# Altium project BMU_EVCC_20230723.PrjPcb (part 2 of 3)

## Sheet BMU_A2_bq79616.SchDoc
size 558 x 431 mm; SheetNumber: 2; SheetTotal: 9
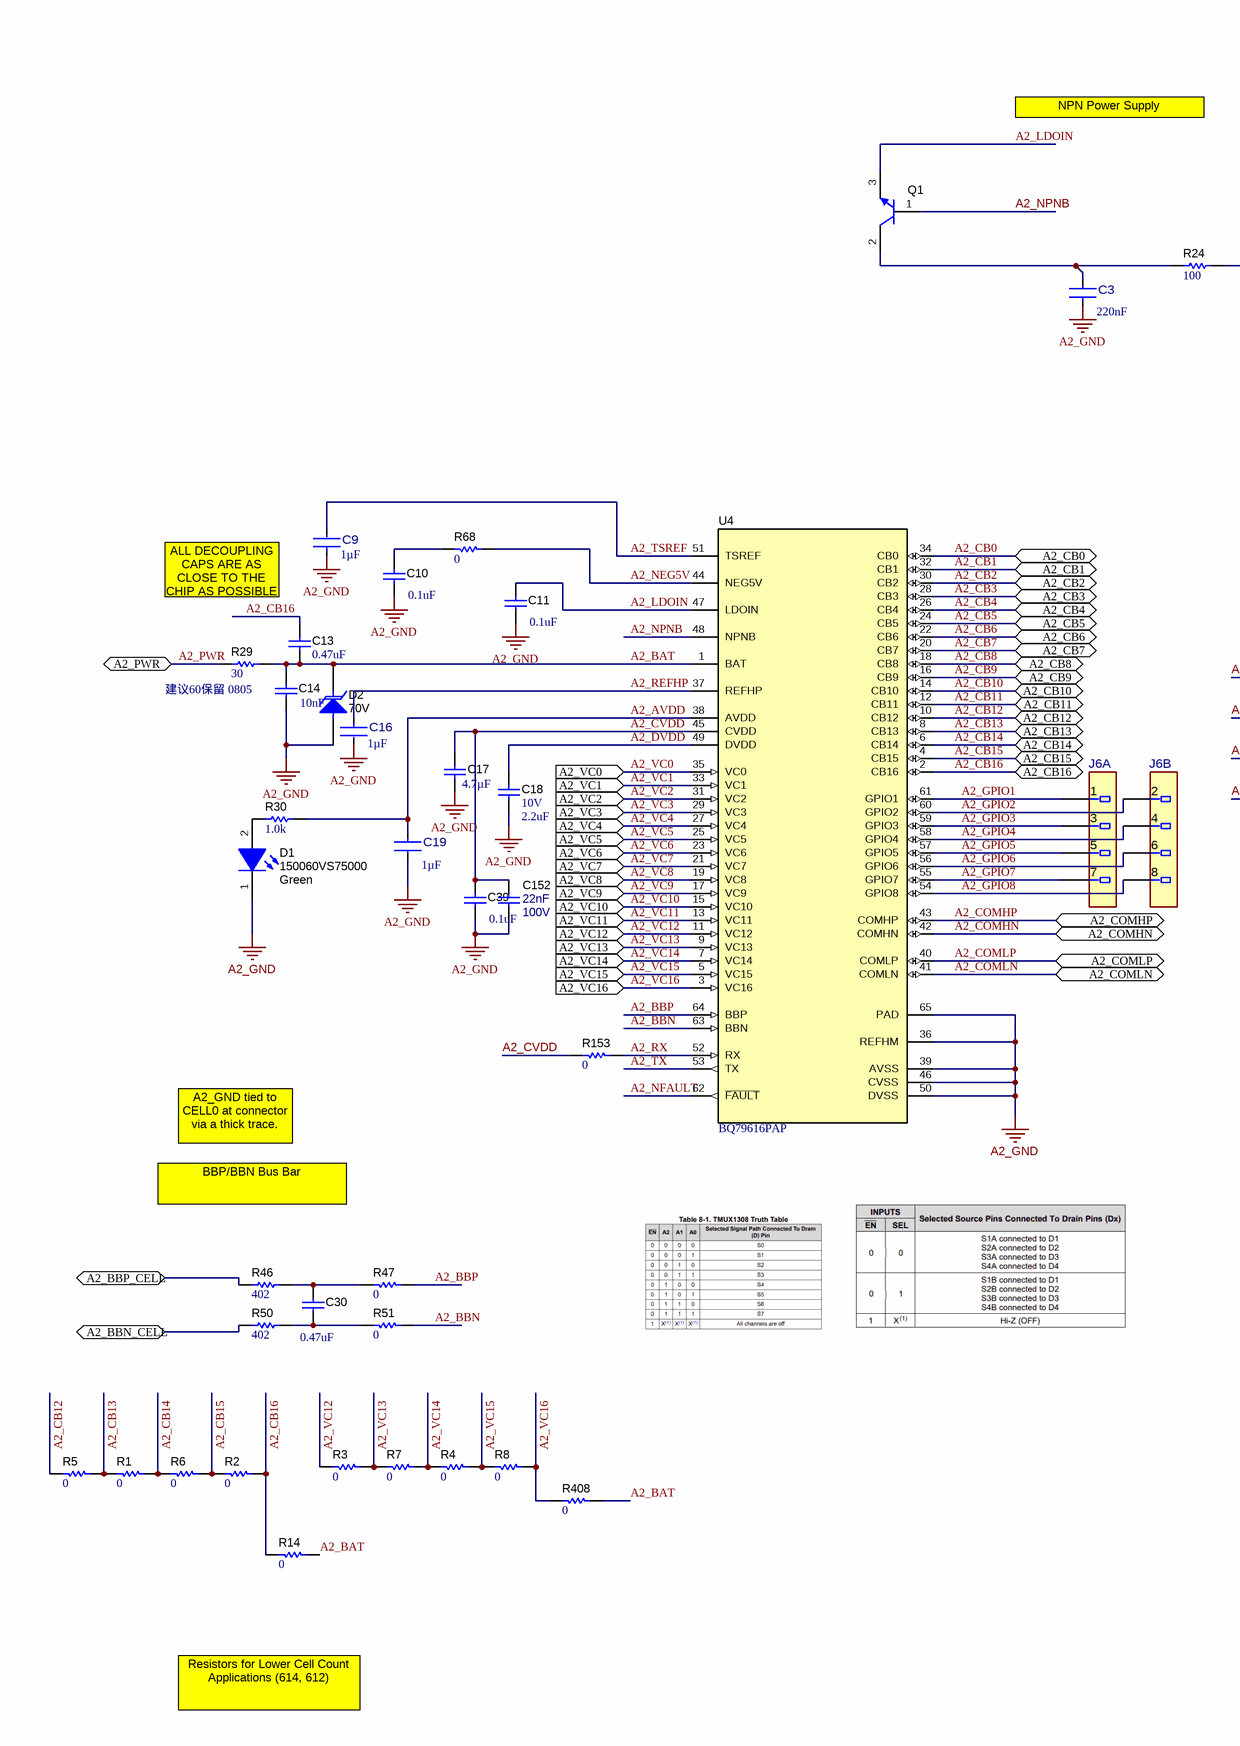
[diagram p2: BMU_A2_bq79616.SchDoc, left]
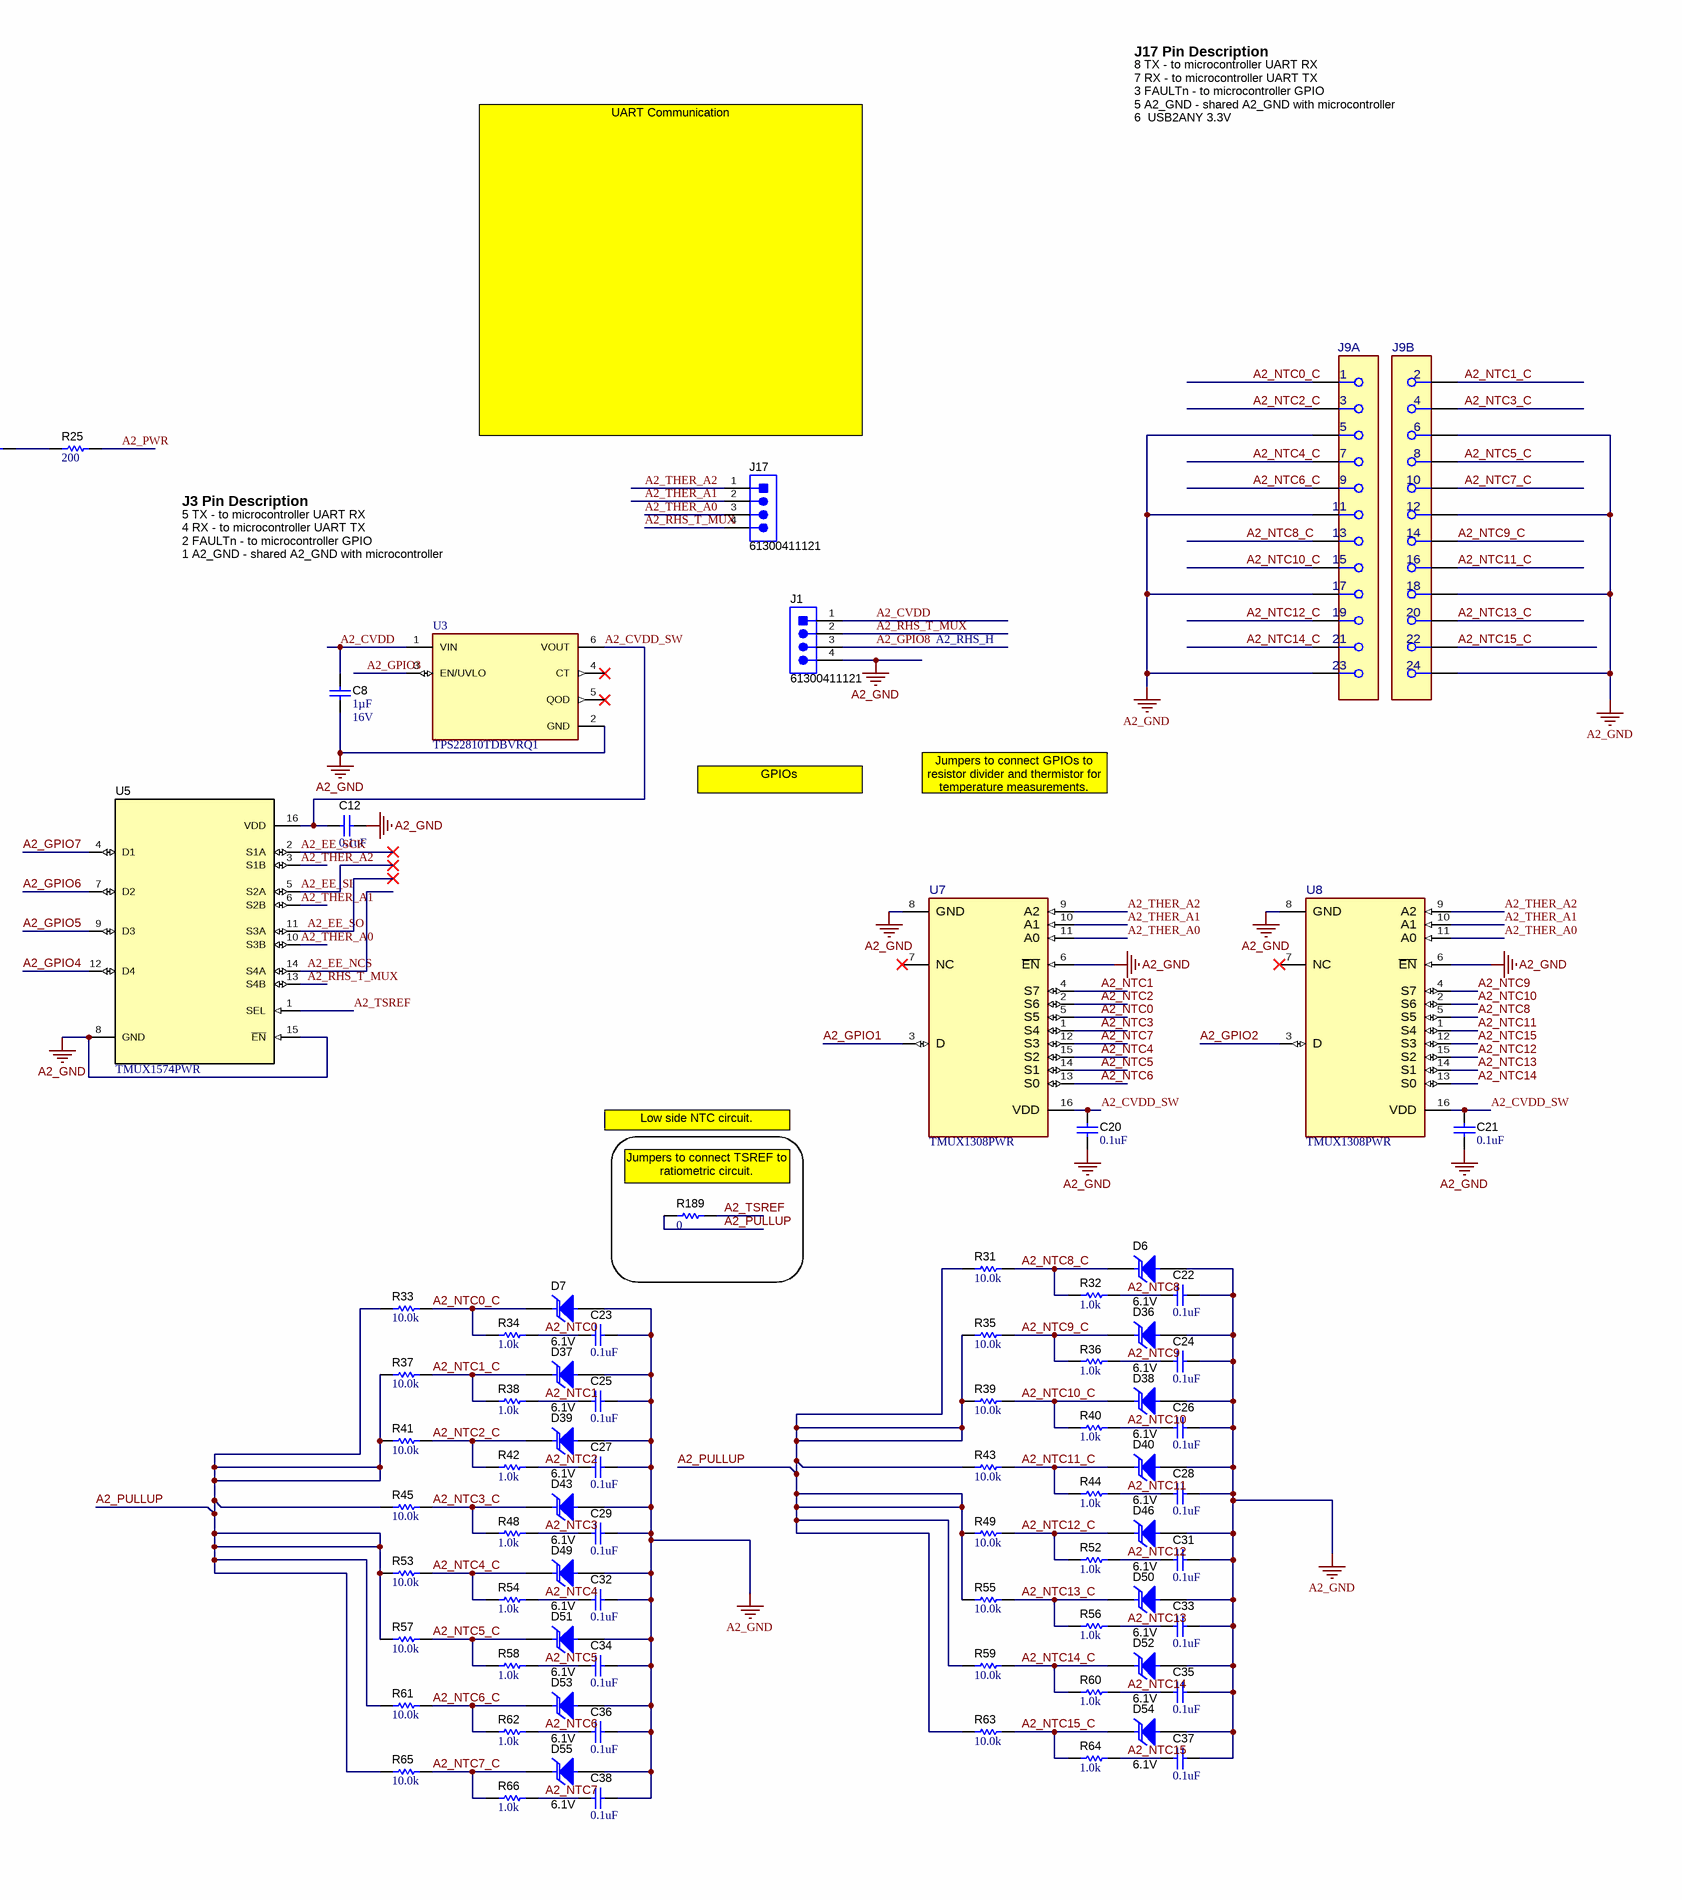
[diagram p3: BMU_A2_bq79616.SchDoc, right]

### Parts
C3  Cap_F: 220nF  [FP-GCM31MR72A224KA37L_1206-MFG]  (hidden comment: GCM31MR72A224KA37L)
C8  Cap_F: 1µF  VDC_V: 16V  [0805_HV]  (hidden comment: GRM21BR71C105KA01L)
C9  Cap_F: 1µF  [FP-C0603C105K8RACAUTO_0603 (1608 Metric)-MFG]  (hidden comment: C0603C105K8RACAUTO)
C10  ValueDisplayed: 0.1uF  [0402]  (hidden comment: GCM155R71A104KA55D)
C11  ValueDisplayed: 0.1uF  [0402]  (hidden comment: GCM155R71A104KA55D)
C12  ValueDisplayed: 0.1uF  [0402]  (hidden comment: GCM155R71H104KE02D)
C13  ValueDisplayed: 0.47uF  [0603]  (hidden comment: GCM188R71C474KA55D)
C14  Cap_F: 10nF  [0603_HV]  (hidden comment: GCM188R72A103KA37J)
C16  Cap_F: 1µF  [FP-C0603C105K8RACAUTO_0603 (1608 Metric)-MFG]  (hidden comment: C0603C105K8RACAUTO)
C17  Cap_F: 4.7µF  [0805_HV]  (hidden comment: C2012X7R1A475M125AC)
C18  VDC_V: 10V  ValueDisplayed: 2.2uF  [0603]  (hidden comment: C0603C225K8PACTU)
C19  Cap_F: 1µF  [FP-C0603C105K8RACAUTO_0603 (1608 Metric)-MFG]  (hidden comment: C0603C105K8RACAUTO)
C20  ValueDisplayed: 0.1uF  [0402]  (hidden comment: GCM155R71H104KE02D)
C21  ValueDisplayed: 0.1uF  [0402]  (hidden comment: GCM155R71H104KE02D)
C22  ValueDisplayed: 0.1uF  [0402]  (hidden comment: GCM155R71H104KE02D)
C23  ValueDisplayed: 0.1uF  [0402]  (hidden comment: GCM155R71H104KE02D)
C24  ValueDisplayed: 0.1uF  [0402]  (hidden comment: GCM155R71H104KE02D)
C25  ValueDisplayed: 0.1uF  [0402]  (hidden comment: GCM155R71H104KE02D)
C26  ValueDisplayed: 0.1uF  [0402]  (hidden comment: GCM155R71H104KE02D)
C27  ValueDisplayed: 0.1uF  [0402]  (hidden comment: GCM155R71H104KE02D)
C28  ValueDisplayed: 0.1uF  [0402]  (hidden comment: GCM155R71H104KE02D)
C29  ValueDisplayed: 0.1uF  [0402]  (hidden comment: GCM155R71H104KE02D)
C30  ValueDisplayed: 0.47uF  [0603]  (hidden comment: GCM188R71C474KA55D)
C31  ValueDisplayed: 0.1uF  [0402]  (hidden comment: GCM155R71H104KE02D)
C32  ValueDisplayed: 0.1uF  [0402]  (hidden comment: GCM155R71H104KE02D)
C33  ValueDisplayed: 0.1uF  [0402]  (hidden comment: GCM155R71H104KE02D)
C34  ValueDisplayed: 0.1uF  [0402]  (hidden comment: GCM155R71H104KE02D)
C35  ValueDisplayed: 0.1uF  [0402]  (hidden comment: GCM155R71H104KE02D)
C36  ValueDisplayed: 0.1uF  [0402]  (hidden comment: GCM155R71H104KE02D)
C37  ValueDisplayed: 0.1uF  [0402]  (hidden comment: GCM155R71H104KE02D)
C38  ValueDisplayed: 0.1uF  [0402]  (hidden comment: GCM155R71H104KE02D)
C39  ValueDisplayed: 0.1uF  [0402]  (hidden comment: GCM155R71A104KA55D)
C152  Cap_F: 22nF  VDC_V: 100V  [0603]  (hidden comment: CGA3E2X7R2A223K080AA)
D1  150060VS75000  value Green  [WL-SMCW_GREEN]
D2  value 70V  [SMA]  (hidden comment: SMAJ70A)
D6  value 6.1V  [ST0201]  (hidden comment: ESDALC6V1-1U2)
D7  value 6.1V  [ST0201]  (hidden comment: ESDALC6V1-1U2)
D36  value 6.1V  [ST0201]  (hidden comment: ESDALC6V1-1U2)
D37  value 6.1V  [ST0201]  (hidden comment: ESDALC6V1-1U2)
D38  value 6.1V  [ST0201]  (hidden comment: ESDALC6V1-1U2)
D39  value 6.1V  [ST0201]  (hidden comment: ESDALC6V1-1U2)
D40  value 6.1V  [ST0201]  (hidden comment: ESDALC6V1-1U2)
D43  value 6.1V  [ST0201]  (hidden comment: ESDALC6V1-1U2)
D46  value 6.1V  [ST0201]  (hidden comment: ESDALC6V1-1U2)
D49  value 6.1V  [ST0201]  (hidden comment: ESDALC6V1-1U2)
D50  value 6.1V  [ST0201]  (hidden comment: ESDALC6V1-1U2)
D51  value 6.1V  [ST0201]  (hidden comment: ESDALC6V1-1U2)
D52  value 6.1V  [ST0201]  (hidden comment: ESDALC6V1-1U2)
D53  value 6.1V  [ST0201]  (hidden comment: ESDALC6V1-1U2)
D54  value 6.1V  [ST0201]  (hidden comment: ESDALC6V1-1U2)
D55  value 6.1V  [ST0201]  (hidden comment: ESDALC6V1-1U2)
J1  61300411121  [WURTH_61300411121]
J6  61300821121  [FP-61300821121_HDR8-MFG]  (value not drawn)  (parts A,B of 2)
J9  SSQ-112-04-G-D  [FP-SSQ-112-04-G-D_CONN_RCPT24-MFG]  (value not drawn)  (parts A,B of 2)
J17  61300411121  [WURTH_61300411121]
Q1  BJT_NPN_C2B1E3  [DPAK]  (value not drawn)
R1  ValueDisplayed: 0  [0603]  (hidden comment: RC0603JR-070RL)
R2  ValueDisplayed: 0  [0603]  (hidden comment: RC0603JR-070RL)
R3  ValueDisplayed: 0  [0603]  (hidden comment: RC0603JR-070RL)
R4  ValueDisplayed: 0  [0603]  (hidden comment: RC0603JR-070RL)
R5  ValueDisplayed: 0  [0603]  (hidden comment: RC0603JR-070RL)
R6  ValueDisplayed: 0  [0603]  (hidden comment: RC0603JR-070RL)
R7  ValueDisplayed: 0  [0603]  (hidden comment: RC0603JR-070RL)
R8  ValueDisplayed: 0  [0603]  (hidden comment: RC0603JR-070RL)
R14  ValueDisplayed: 0  [0603]  (hidden comment: RC0603JR-070RL)
R24  ValueDisplayed: 100  [2010]  (hidden comment: CRCW2010100RFKEF)
R25  ValueDisplayed: 200  [2010]  (hidden comment: CRCW2010200RFKEF)
R29  ValueDisplayed: 30  [0805_HV]  (hidden comment: CRCW080530R0JNEA)
R30  ValueDisplayed: 1.0k  [0603]  (hidden comment: CRCW06031K00JNEA)
R31  ValueDisplayed: 10.0k  [0603]  (hidden comment: CRCW060310K0FKEA)
R32  ValueDisplayed: 1.0k  [0402]  (hidden comment: CRCW04021K00JNED)
R33  ValueDisplayed: 10.0k  [0603]  (hidden comment: CRCW060310K0FKEA)
R34  ValueDisplayed: 1.0k  [0402]  (hidden comment: CRCW04021K00JNED)
R35  ValueDisplayed: 10.0k  [0603]  (hidden comment: CRCW060310K0FKEA)
R36  ValueDisplayed: 1.0k  [0402]  (hidden comment: CRCW04021K00JNED)
R37  ValueDisplayed: 10.0k  [0603]  (hidden comment: CRCW060310K0FKEA)
R38  ValueDisplayed: 1.0k  [0402]  (hidden comment: CRCW04021K00JNED)
R39  ValueDisplayed: 10.0k  [0603]  (hidden comment: CRCW060310K0FKEA)
R40  ValueDisplayed: 1.0k  [0402]  (hidden comment: CRCW04021K00JNED)
R41  ValueDisplayed: 10.0k  [0603]  (hidden comment: CRCW060310K0FKEA)
R42  ValueDisplayed: 1.0k  [0402]  (hidden comment: CRCW04021K00JNED)
R43  ValueDisplayed: 10.0k  [0603]  (hidden comment: CRCW060310K0FKEA)
R44  ValueDisplayed: 1.0k  [0402]  (hidden comment: CRCW04021K00JNED)
R45  ValueDisplayed: 10.0k  [0603]  (hidden comment: CRCW060310K0FKEA)
R46  ValueDisplayed: 402  [0603]  (hidden comment: CRCW0603402RFKEA)
R47  ValueDisplayed: 0  [0603]  (hidden comment: RC0603JR-070RL)
R48  ValueDisplayed: 1.0k  [0402]  (hidden comment: CRCW04021K00JNED)
R49  ValueDisplayed: 10.0k  [0603]  (hidden comment: CRCW060310K0FKEA)
R50  ValueDisplayed: 402  [0603]  (hidden comment: CRCW0603402RFKEA)
R51  ValueDisplayed: 0  [0603]  (hidden comment: RC0603JR-070RL)
R52  ValueDisplayed: 1.0k  [0402]  (hidden comment: CRCW04021K00JNED)
R53  ValueDisplayed: 10.0k  [0603]  (hidden comment: CRCW060310K0FKEA)
R54  ValueDisplayed: 1.0k  [0402]  (hidden comment: CRCW04021K00JNED)
R55  ValueDisplayed: 10.0k  [0603]  (hidden comment: CRCW060310K0FKEA)
R56  ValueDisplayed: 1.0k  [0402]  (hidden comment: CRCW04021K00JNED)
R57  ValueDisplayed: 10.0k  [0603]  (hidden comment: CRCW060310K0FKEA)
R58  ValueDisplayed: 1.0k  [0402]  (hidden comment: CRCW04021K00JNED)
R59  ValueDisplayed: 10.0k  [0603]  (hidden comment: CRCW060310K0FKEA)
R60  ValueDisplayed: 1.0k  [0402]  (hidden comment: CRCW04021K00JNED)
R61  ValueDisplayed: 10.0k  [0603]  (hidden comment: CRCW060310K0FKEA)
R62  ValueDisplayed: 1.0k  [0402]  (hidden comment: CRCW04021K00JNED)
R63  ValueDisplayed: 10.0k  [0603]  (hidden comment: CRCW060310K0FKEA)
R64  ValueDisplayed: 1.0k  [0402]  (hidden comment: CRCW04021K00JNED)
R65  ValueDisplayed: 10.0k  [0603]  (hidden comment: CRCW060310K0FKEA)
R66  ValueDisplayed: 1.0k  [0402]  (hidden comment: CRCW04021K00JNED)
R68  ValueDisplayed: 0  [0603]  (hidden comment: RC0603JR-070RL)
R153  ValueDisplayed: 0  [0603]  (hidden comment: RC0603JR-070RL)
R189  ValueDisplayed: 0  [0402]  (hidden comment: CRCW04020000Z0ED)
R408  ValueDisplayed: 0  [0603]  (hidden comment: RC0603JR-070RL)
U3  TPS22810TDBVRQ1  [FP-DBV0006A-MFG]
U4  PartNumber: BQ79616PAP  [PAP0064F-MFG]  (hidden comment: BQ79616PAPQ1)
U5  TMUX1574PWR  [PW0016A_N]
U7  TMUX1308PWR  [PW0016A-MFG]
U8  TMUX1308PWR  [PW0016A-MFG]

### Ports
A2_BBN_CELL (bidir), A2_BBP_CELL (bidir), A2_CB0 (bidir), A2_CB1 (bidir), A2_CB2 (bidir), A2_CB3 (bidir), A2_CB4 (bidir), A2_CB5 (bidir), A2_CB6 (bidir), A2_CB7 (bidir), A2_CB8 (bidir), A2_CB9 (bidir), A2_CB10 (bidir), A2_CB11 (bidir), A2_CB12 (bidir), A2_CB13 (bidir), A2_CB14 (bidir), A2_CB15 (bidir), A2_CB16 (bidir), A2_COMHN (bidir), A2_COMHP (bidir), A2_COMLN (bidir), A2_COMLP (bidir), A2_PWR (bidir), A2_VC0 (in), A2_VC1 (in), A2_VC2 (in), A2_VC3 (in), A2_VC4 (in), A2_VC5 (in), A2_VC6 (in), A2_VC7 (in), A2_VC8 (in), A2_VC9 (in), A2_VC10 (in), A2_VC11 (in), A2_VC12 (in), A2_VC13 (in), A2_VC14 (in), A2_VC15 (in), A2_VC16 (in)

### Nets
A2_GND: C3.1 C8.2 C9.2 C10.1 C11.1 C12.1 C14.2 C16.1 C17.2 C18.1 C19.1 C20.2 C21.2 C22.2 C23.2 C24.2 C25.2 C26.2 C27.2 C28.2 C29.2 C31.2 C32.2 C33.2 C34.2 C35.2 C36.2 C37.2 C38.2 C39.1 C152.2 D1.1(K) D2.2(A) D6.2(A) D7.2(A) D36.2(A) D37.2(A) D38.2(A) D39.2(A) D40.2(A) D43.2(A) D46.2(A) D49.2(A) D50.2(A) D51.2(A) D52.2(A) D53.2(A) D54.2(A) D55.2(A) J1.4 J9.5 J9.6 J9.11 J9.12 J9.17 J9.18 J9.23 J9.24 U3.2(GND) U4.36(REFHM) U4.39(AVSS) U4.46(CVSS) U4.50(DVSS) U4.65(PAD) U5.8(GND) U5.15(~{EN}) U7.6(~{EN}) U7.8(GND) U8.6(~{EN}) U8.8(GND)
A2_AVDD: C19.2 R30.2 U4.38(AVDD)
A2_BAT: C13.2 C14.1 D2.1(K) R14.1 R29.2 R408.1 U4.1(BAT)
A2_BBN: R51.1 U4.63(BBN)
A2_BBN_CELL: R50.1 ; port A2_BBN_CELL
A2_BBP: R47.1 U4.64(BBP)
A2_BBP_CELL: R46.1 ; port A2_BBP_CELL
A2_CB0: U4.34(CB0) ; port A2_CB0
A2_CB1: U4.32(CB1) ; port A2_CB1
A2_CB2: U4.30(CB2) ; port A2_CB2
A2_CB3: U4.28(CB3) ; port A2_CB3
A2_CB4: U4.26(CB4) ; port A2_CB4
A2_CB5: U4.24(CB5) ; port A2_CB5
A2_CB6: U4.22(CB6) ; port A2_CB6
A2_CB7: U4.20(CB7) ; port A2_CB7
A2_CB8: U4.18(CB8) ; port A2_CB8
A2_CB9: U4.16(CB9) ; port A2_CB9
A2_CB10: U4.14(CB10) ; port A2_CB10
A2_CB11: U4.12(CB11) ; port A2_CB11
A2_CB12: R5.2 U4.10(CB12) ; port A2_CB12
A2_CB13: R1.2 R5.1 U4.8(CB13) ; port A2_CB13
A2_CB14: R1.1 R6.2 U4.6(CB14) ; port A2_CB14
A2_CB15: R2.2 R6.1 U4.4(CB15) ; port A2_CB15
A2_CB16: C13.1 R2.1 R14.2 U4.2(CB16) ; port A2_CB16
A2_COMHN: U4.42(COMHN) ; port A2_COMHN
A2_COMHP: U4.43(COMHP) ; port A2_COMHP
A2_COMLN: U4.41(COMLN) ; port A2_COMLN
A2_COMLP: U4.40(COMLP) ; port A2_COMLP
A2_CVDD: C8.1 C17.1 C39.2 C152.1 J1.1 R153.2 U3.1(VIN) U4.45(CVDD)
A2_CVDD_SW: C12.2 C20.1 C21.1 U3.6(VOUT) U5.16(VDD) U7.16(VDD) U8.16(VDD)
A2_DVDD: C18.2 U4.49(DVDD)
A2_EE_NCS: U5.14(S4A)
A2_EE_SCK: U5.2(S1A)
A2_EE_SI: U5.5(S2A)
A2_EE_SO: U5.11(S3A)
A2_GPIO1: J6.1 U4.61(GPIO1) U7.3(D)
A2_GPIO2: J6.2 U4.60(GPIO2) U8.3(D)
A2_GPIO3: J6.3 U3.3(EN/UVLO) U4.59(GPIO3)
A2_GPIO4: J6.4 U4.58(GPIO4) U5.12(D4)
A2_GPIO5: J6.5 U4.57(GPIO5) U5.9(D3)
A2_GPIO6: J6.6 U4.56(GPIO6) U5.7(D2)
A2_GPIO7: J6.7 U4.55(GPIO7) U5.4(D1)
A2_GPIO8: J1.3 J6.8 U4.54(GPIO8)
A2_LDOIN: C11.2 Q1.3(E) U4.47(LDOIN)
A2_NEG5V: R68.1 U4.44(NEG5V)
A2_NFAULT: U4.62(~{FAULT})
A2_NPNB: Q1.1(B) U4.48(NPNB)
A2_NTC0: C23.1 R34.2 U7.5(S5)
A2_NTC0_C: D7.1(K) J9.1 R33.2 R34.1
A2_NTC1: C25.1 R38.2 U7.4(S7)
A2_NTC1_C: D37.1(K) J9.2 R37.2 R38.1
A2_NTC2: C27.1 R42.2 U7.2(S6)
A2_NTC2_C: D39.1(K) J9.3 R41.2 R42.1
A2_NTC3: C29.1 R48.2 U7.1(S4)
A2_NTC3_C: D43.1(K) J9.4 R45.2 R48.1
A2_NTC4: C32.1 R54.2 U7.15(S2)
A2_NTC4_C: D49.1(K) J9.7 R53.2 R54.1
A2_NTC5: C34.1 R58.2 U7.14(S1)
A2_NTC5_C: D51.1(K) J9.8 R57.2 R58.1
A2_NTC6: C36.1 R62.2 U7.13(S0)
A2_NTC6_C: D53.1(K) J9.9 R61.2 R62.1
A2_NTC7: C38.1 R66.2 U7.12(S3)
A2_NTC7_C: D55.1(K) J9.10 R65.2 R66.1
A2_NTC8: C22.1 R32.2 U8.5(S5)
A2_NTC8_C: D6.1(K) J9.13 R31.2 R32.1
A2_NTC9: C24.1 R36.2 U8.4(S7)
A2_NTC9_C: D36.1(K) J9.14 R35.2 R36.1
A2_NTC10: C26.1 R40.2 U8.2(S6)
A2_NTC10_C: D38.1(K) J9.15 R39.2 R40.1
A2_NTC11: C28.1 R44.2 U8.1(S4)
A2_NTC11_C: D40.1(K) J9.16 R43.2 R44.1
A2_NTC12: C31.1 R52.2 U8.15(S2)
A2_NTC12_C: D46.1(K) J9.19 R49.2 R52.1
A2_NTC13: C33.1 R56.2 U8.14(S1)
A2_NTC13_C: D50.1(K) J9.20 R55.2 R56.1
A2_NTC14: C35.1 R60.2 U8.13(S0)
A2_NTC14_C: D52.1(K) J9.21 R59.2 R60.1
A2_NTC15: C37.1 R64.2 U8.12(S3)
A2_NTC15_C: D54.1(K) J9.22 R63.2 R64.1
A2_PULLUP: R31.1 R33.1 R35.1 R37.1 R39.1 R41.1 R43.1 R45.1 R49.1 R53.1 R55.1 R57.1 R59.1 R61.1 R63.1 R65.1 R189.1
A2_PWR: R25.2 R29.1 ; port A2_PWR
A2_REFHP: C16.2 U4.37(REFHP)
A2_RHS_T_MUX: J1.2 J17.4 U5.13(S4B)
A2_RX: R153.1 U4.52(RX)
A2_THER_A0: J17.3 U5.10(S3B) U7.11(A0) U8.11(A0)
A2_THER_A1: J17.2 U5.6(S2B) U7.10(A1) U8.10(A1)
A2_THER_A2: J17.1 U5.3(S1B) U7.9(A2) U8.9(A2)
A2_TSREF: C9.1 R189.2 U4.51(TSREF) U5.1(SEL)
A2_TX: U4.53(TX)
A2_VC0: U4.35(VC0) ; port A2_VC0
A2_VC1: U4.33(VC1) ; port A2_VC1
A2_VC2: U4.31(VC2) ; port A2_VC2
A2_VC3: U4.29(VC3) ; port A2_VC3
A2_VC4: U4.27(VC4) ; port A2_VC4
A2_VC5: U4.25(VC5) ; port A2_VC5
A2_VC6: U4.23(VC6) ; port A2_VC6
A2_VC7: U4.21(VC7) ; port A2_VC7
A2_VC8: U4.19(VC8) ; port A2_VC8
A2_VC9: U4.17(VC9) ; port A2_VC9
A2_VC10: U4.15(VC10) ; port A2_VC10
A2_VC11: U4.13(VC11) ; port A2_VC11
A2_VC12: R3.2 U4.11(VC12) ; port A2_VC12
A2_VC13: R3.1 R7.2 U4.9(VC13) ; port A2_VC13
A2_VC14: R4.2 R7.1 U4.7(VC14) ; port A2_VC14
A2_VC15: R4.1 R8.2 U4.5(VC15) ; port A2_VC15
A2_VC16: R8.1 R408.2 U4.3(VC16) ; port A2_VC16
NetC3_2: C3.2 Q1.2(C) R24.1
NetC10_2: C10.2 R68.2
NetC30_1: C30.1 R46.2 R47.2
NetC30_2: C30.2 R50.2 R51.2
NetD1_2: D1.2(A) R30.1
NetR24_2: R24.2 R25.1

Not connected (* = marked no-connect by the designer): U3 4(CT)* 5(QOD)*; U7 7(NC)*; U8 7(NC)*

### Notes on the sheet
- J17 Pin Description
- 8 TX - to microcontroller UART RX
- 7 RX - to microcontroller UART TX
- 3 FAULTn - to microcontroller GPIO
- 5 A2_GND - shared A2_GND with microcontroller
- 6  USB2ANY 3.3V
- NPN Power Supply
- UART Communication
- J3 Pin Description
- 5 TX - to microcontroller UART RX
- 4 RX - to microcontroller UART TX
- 2 FAULTn - to microcontroller GPIO
- 1 A2_GND - shared A2_GND with microcontroller
- A2_RHS_H
- ALL DECOUPLING CAPS ARE AS CLOSE TO THE CHIP AS POSSIBLE
- GPIOs
- Jumpers to connect GPIOs to resistor divider and thermistor for temperature measurements.
- (near R29) 建议60保留 0805
- Low side NTC circuit.
- (near R189) Jumpers to connect TSREF to ratiometric circuit.
- A2_GND tied to CELL0 at connector via a thick trace.
- BBP/BBN Bus Bar
- Resistors for Lower Cell Count Applications (614, 612)

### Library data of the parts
C3 = CMP-0087125-1: Multilayer Ceramic Capacitors MLCC - SMD/SMT 1206 0.22uF 100volts X7R +/-10%; Manufacturer: Murata; TempCo: 15%; Tolerance_%: 10%; SizeZ_mm: 1.25mm; AEC Qualified: Yes; VDC_V: 100V; AEC Grade: Grade 1
C8 = CMP-0008323-2: CAP, CERM, 1 uF, 16 V, +/- 10%, X7R, 0805; Manufacturer: MuRata; TaMin_C: -55°C; ESR_ohm: 3m; Polarized: N; SizeAreaWB_mm2: 6.75; Value1: 0.003 ohm; U/M: EA; Value: 1uF; TaMax_C: 125°C; SizeZ_mm: 1.45; SizeX_mm: 2; SizeY_mm: 1.25; Cap_Case: 0805; SizeArea_mm2: 2.5; AEC Category: Q200
C9 C16 C19 = CMP-0087157-1: CAP CER 0603 1UF 10V X7R 10%; Manufacturer: KEMET; AEC Grade: Grade 1; TempCo: 15%; AEC Qualified: Yes; SizeZ_mm: 0.95mm
C10 C11 C39 = CMP-0006350-2: CAP, CERM, 0.1 uF, 10 V, +/- 10%, X7R, AEC-Q200 Grade 1, 0402; Manufacturer: MuRata; TaMin_C: -55°C; Polarized: N; SizeAreaWB_mm2: 3; Value1: Unknown; U/M: EA; Value: 0.1uF; TaMax_C: 125°C; SizeZ_mm: 0.6; SizeX_mm: 1; SizeY_mm: 0.5; Value2: 10V; AEC Qualified: Y; Cap_F: 100nF; AEC Category: Q200
C12 C20-C29 C31-C38 = CMP-0006356-2: CAP, CERM, 0.1 uF, 50 V, +/- 10%, X7R, AEC-Q200 Grade 1, 0402; Manufacturer: MuRata; TaMin_C: -55°C; Polarized: N; SizeAreaWB_mm2: 3; Value1: Unknown; U/M: EA; Value: 0.1uF; TaMax_C: 125°C; SizeZ_mm: 0.6; SizeX_mm: 1; SizeY_mm: 0.5; Value2: 50V; AEC Qualified: Y; Cap_F: 100nF; AEC Category: Q200
C13 C30 = CMP-0007138-4: CAP, CERM, 0.47 uF, 16 V, +/- 10%, X7R, AEC-Q200 Grade 1, 0603; Manufacturer: MuRata; Polarized: N; Value: 0.47uF; U/M: EA; Cap_F: 470nF; Value1: Unknown; VDC_V: 16V; TaMin_C: -55°C; TaMax_C: 125°C; AEC Category: Q200; AEC Qualified: Y; AEC Grade: 1; SizeArea_mm2: 1.28; SizeAreaWB_mm2: 4.68; SizeX_mm: 1.6; SizeY_mm: 0.8
C14 = CMP-0084773-1: CAP, CERM, 0.01 µF, 100 V,+/- 10%, X7R, AEC-Q200 Grade 1, 0603; Manufacturer: MuRata; SizeArea_mm2: 1.28; ValueDisplayed: 0.01µF; Polarized: N; AEC Grade: 1; Value2: 100V; SizeY_mm: 0.8; Cap_Case: 0603; TaMax_C: 125°C; Value: 0.01uF; SizeAreaWB_mm2: 4.68; TaMin_C: -55°C; AEC Category: Q200; U/M: EA; AEC Qualified: Y; SizeX_mm: 1.6
C17 = CMP-0007865-2: CAP, CERM, 4.7 uF, 10 V, +/- 20%, X7R, 0805; Manufacturer: TDK; AEC Qualified: N; SizeZ_mm: 1.45; VDC_V: 10V; TaMin_C: -55°C; SizeAreaWB_mm2: 6.75; Value1: Unknown; U/M: EA; Value: 4.7uF; TaMax_C: 125°C; SizeX_mm: 2; SizeY_mm: 1.25; Cap_Case: 0805; SizeArea_mm2: 2.5; AEC Category: Q200
C18 = CMP-0006906-5: CAP, CERM, 2.2 uF, 10 V, +/- 10%, X5R, 0603; Manufacturer: Kemet; TaMin_C: -55°C; Polarized: N; SizeAreaWB_mm2: 4.68; Value1: Unknown; U/M: EA; Value: 2.2uF; TaMax_C: 85°C; SizeZ_mm: 1; SizeX_mm: 1.6; SizeY_mm: 0.8; SizeArea_mm2: 1.28; Cap_F: 2.2µF; AEC Category: Q200
C152 = CMP-0007086-4: CAP, CERM, 0.022 uF, 100 V, +/- 10%, X7R, AEC-Q200 Grade 1, 0603; Manufacturer: TDK; TaMin_C: -55°C; ESR_ohm: 0.083542; Polarized: N; SizeAreaWB_mm2: 4.68; Value1: 0.083542 ohm; U/M: EA; TaMax_C: 125°C; SizeZ_mm: 1; SizeX_mm: 1.6; SizeY_mm: 0.8; SizeArea_mm2: 1.28; AEC Qualified: Y; IRMS_A: 6.09312dA; AEC Category: Q200
D1 = CMP-0002894-2: LED, Green, SMD; Manufacturer: Wurth Elektronik; Type: AlInGaP; Value2: 2V; Io_A: 20mA; Value1: W
D2 = CMP-0084973-1: Diode, TVS, Uni, 70 V, 113 Vc, 400 W, 3.5 A, SMA; Manufacturer: Wurth Elektronik; PartNumber: 824500701; Vc: 113V; SizeY_mm: 2.92; RJA_CperW: 120; Ppk: 400W; SizeZ_mm: 2.87; AEC Qualified: N; Vbr_Min: 77.8V; SizeAreaWB_mm2: 37.3428; Ipp: 3.5A; SizeArea_mm2: 16.3228; AEC Category: Q101; SizeX_mm: 5.59; Vbr_Max: 86V
D6 D7 D36-D40 D43 D46 D49-D55 = CMP-0006069-3: Diode, TVS, Uni, 6.1 V, 0201; Manufacturer: Texas Instruments; PartNumber: ESD441DPLR; SizeX_mm: 0.6; Ppk: 20W; SizeY_mm: 0.3; Ipp: 2A; SizeAreaWB_mm2: 2.08; SizeArea_mm2: 0.18; Vbr_Max: 8V; AEC Qualified: N; SizeZ_mm: 0.33; AEC Category: Q101
J1 J17 = CMP-0054798-2: Header, 2.54 mm, 4x1, Gold, TH; Manufacturer: Wurth Elektronik; Pitch_mm: 2.54; Gender: Male; Row_Count: 1; Cert_UL: Y; Shrouded: N
J6 = CMP-0087153-1: CONN HEADER VERT 8POS 2.54MM; Manufacturer: Wurth Elektronik; Voltage_V: 250V; Row_Count: 2; Current_A: 3A; ContactFinish: Gold
J9 = CMP-0096812-1: 24 Position Receptacle Connector 0.100" (2.54mm) Through Hole Gold; Part Number: 61302421121; Manufacturer: Wurth Elektronik; Conn Orientation: Vertical; ContactFinish: Gold,Nickel; SizeZ_mm: 8.64mm; AEC Qualified: No; Voltage_V: 655V; Conn Gender: Female; Is Female: yes; Row_Count: 2
Q1 = CMP-0000504-4: Transistor, NPN, 150 V, 1 A, AEC-Q101, DPAK; Manufacturer: Diodes Inc.; PartNumber: ZXTN4004KTC; CompType: BJT; IcRated_A: 1A; PNP: 0; SizeArea_mm2: 64.8114; TaMax_C: 150°C; Vceo_V: 150V; TaMin_C: -55°C; SizeX_mm: 9.91; SizeY_mm: 6.54; SizeZ_mm: 2.29; Value1: 1 A; AEC Category: Q101; Vcesat1_V: 250mV; NPN: 1; SizeAreaWB_mm2: 101.7114; AEC Qualified: Y; Value: 150 V
R1-R8 R14 R47 R51 R68 R153 R408 = CMP-0025885-5: RES, 0, 5%, 0.1 W, 0603; Manufacturer: Yageo; Power_W: 100mW; TempCo: 200 ppm/C; Value_Code: 0000; Value: 0; EIA_Code: E24; SizeX_mm: 1.6; SizeY_mm: 0.8; SizeZ_mm: 1; Value2: 0.1W; SizeArea_mm2: 1.28; AEC Qualified: N; VDC_V: 75V; AEC Category: Q200; SizeAreaWB_mm2: 4.68
R24 = CMP-0016209-3: RES, 100, 1%, 0.75 W, AEC-Q200 Grade 0, 2010; Manufacturer: Vishay-Dale; Power_W: 750mW; TempCo: 100 ppm/C; Value_Code: 100R; Value: 100; EIA_Code: E96; SizeX_mm: 5; SizeY_mm: 2.5; SizeZ_mm: 1.66; Value2: 0.75W; SizeArea_mm2: 12.5; AEC Qualified: Y; VDC_V: 400V; AEC Category: Q200; AEC Grade: 0
R25 = CMP-0016302-3: RES, 200, 1%, 0.75 W, AEC-Q200 Grade 0, 2010; Manufacturer: Vishay-Dale; Power_W: 750mW; TempCo: 100 ppm/C; Value_Code: 200R; Value: 200; EIA_Code: E96; SizeX_mm: 5; SizeY_mm: 2.5; SizeZ_mm: 1.66; Value2: 0.75W; SizeArea_mm2: 12.5; AEC Qualified: Y; VDC_V: 400V; AEC Category: Q200; AEC Grade: 0
R29 = CMP-0020525-3: RES, 30, 5%, 0.125 W, AEC-Q200 Grade 0, 0805; Manufacturer: Vishay-Dale; Power_W: 125mW; TempCo: 200 ppm/C; Value_Code: 30R0; Value: 30; EIA_Code: E24; SizeX_mm: 2; SizeY_mm: 1.25; SizeZ_mm: 1.45; Value2: 0.125W; SizeArea_mm2: 2.5; AEC Qualified: Y; VDC_V: 150V; AEC Category: Q200; AEC Grade: 0
R30 = CMP-0025729-4: RES, 1.0 k, 5%, 0.1 W, AEC-Q200 Grade 0, 0603; Manufacturer: Vishay-Dale; Value: 1.0k; Res_ohm: 1k; Value_Code: 1k00; Power_W: 100mW; Value2: 0.1W; VDC_V: 75V; TempCo: 200 ppm/C; EIA_Code: E24; SizeArea_mm2: 1.28; SizeX_mm: 1.6; SizeY_mm: 0.8; SizeZ_mm: 1; AEC Category: Q200; AEC Qualified: Y; AEC Grade: 0
R31 R33 R35 R37 R39 R41 R43 R45 R49 R53 R55 R57 R59 R61 R63 R65 = CMP-0021998-4: RES, 10.0 k, 1%, 0.1 W, AEC-Q200 Grade 0, 0603; Manufacturer: Vishay-Dale; Power_W: 100mW; TempCo: 100 ppm/C; Value_Code: 10k0; Value: 10.0k; EIA_Code: E96; Res_ohm: 10k; SizeX_mm: 1.6; SizeY_mm: 0.8; SizeZ_mm: 1; Value2: 0.1W; SizeArea_mm2: 1.28; AEC Qualified: Y; VDC_V: 75V; AEC Category: Q200; AEC Grade: 0
R32 R34 R36 R38 R40 R42 R44 R48 R52 R54 R56 R58 R60 R62 R64 R66 = CMP-0026852-3: RES, 1.0 k, 5%, 0.063 W, AEC-Q200 Grade 0, 0402; Manufacturer: Vishay-Dale; Power_W: 63mW; TempCo: 200 ppm/C; Value_Code: 1k00; Value: 1.0k; EIA_Code: E24; Res_ohm: 1k; SizeX_mm: 1; SizeY_mm: 0.5; SizeZ_mm: 0.6; Value2: 0.063W; AEC Qualified: Y; VDC_V: 50V; AEC Category: Q200; AEC Grade: 0
R46 R50 = CMP-0022409-5: RES, 402, 1%, 0.1 W, AEC-Q200 Grade 0, 0603; Manufacturer: Vishay-Dale; Power_W: 100mW; TempCo: 100 ppm/C; Value_Code: 402R; Value: 402; EIA_Code: E96; SizeX_mm: 1.6; SizeY_mm: 0.8; SizeZ_mm: 1; Value2: 0.1W; SizeArea_mm2: 1.28; AEC Qualified: Y; VDC_V: 75V; AEC Grade: 0; AEC Category: Q200
R189 = CMP-0026822-3: RES, 0, 5%, 0.063 W, AEC-Q200 Grade 0, 0402; Manufacturer: Vishay-Dale; Power_W: 63mW; TempCo: 200 ppm/C; Value_Code: 0000; Value: 0; EIA_Code: E24; SizeX_mm: 1; SizeY_mm: 0.5; SizeZ_mm: 0.6; Value2: 0.063W; AEC Qualified: Y; VDC_V: 50V; AEC Category: Q200
U3 = CMP-04910-000007-1: IC PWR SWITCH N-CHAN 1:1 SOT23-6; Manufacturer: Texas Instruments; Max Supply Voltage: 18V; Standoff Height: 0mm; Nominal Supply Current: 49-62uA; Automotive Grade: Grade 2; Min Supply Voltage: 2.7V; Max Junction Temp: +150°C; Number Of Outputs: 1
U4 = CMP-0750035-3: SafeTI™ Precision Monitor With Integrated Hardware Protector for Lithium-Ion, Lithium Phosphate, Lithium Titanate Battery Pack, PAP0064F (HTQFP-64); Manufacturer: Texas Instruments; SizeX_mm: 12; SizeArea_mm2: 144; SizeAreaWB_mm2: 196; AEC Qualified: Y; SizeZ_mm: 1.2; AEC Category: Q200; CompType: IC
U5 = CMP-0086166-2: Low-capacitance, 2:1 (SPDT) 4-channel, powered-off protection switch with 1.8 V logic, PW0016A (TSSOP-16); Alternate Manufacturer: Texas Instruments; AEC Qualified: N; Rating: Catalog; SizeZ_mm: 1.2; CompType: IC; SizeArea_mm2: 32; AEC Category: Q200; SizeY_mm: 5; SizeAreaWB_mm2: 58.8; SizeX_mm: 6.4
U7 U8 = CMP-0090991-1: 5-V, 8: 1, 1-channel general-purpose multiplexer with 1.8-V logic control 16-TSSOP -40 to 125; Manufacturer: Texas Instruments; Max Supply Voltage: 5.5V; AEC Qualified: No; PositionCount: 1; Min Supply Voltage: 1.62V; -3Db Bandwith: 350-500MHz; Mux Demux Ratio: 8:1; Nominal Supply Current: 1uA; SizeZ_mm: 1.2mm; TaMin_C: -40°C; TaMax_C: +125°C; Standoff Height: 0.05mm; TJmax_C: +150°C; On State Resistance: 75-650Ω

## Sheet Transf_BMS_Communications.SchDoc
size C; SheetNumber: 5; SheetTotal: 9
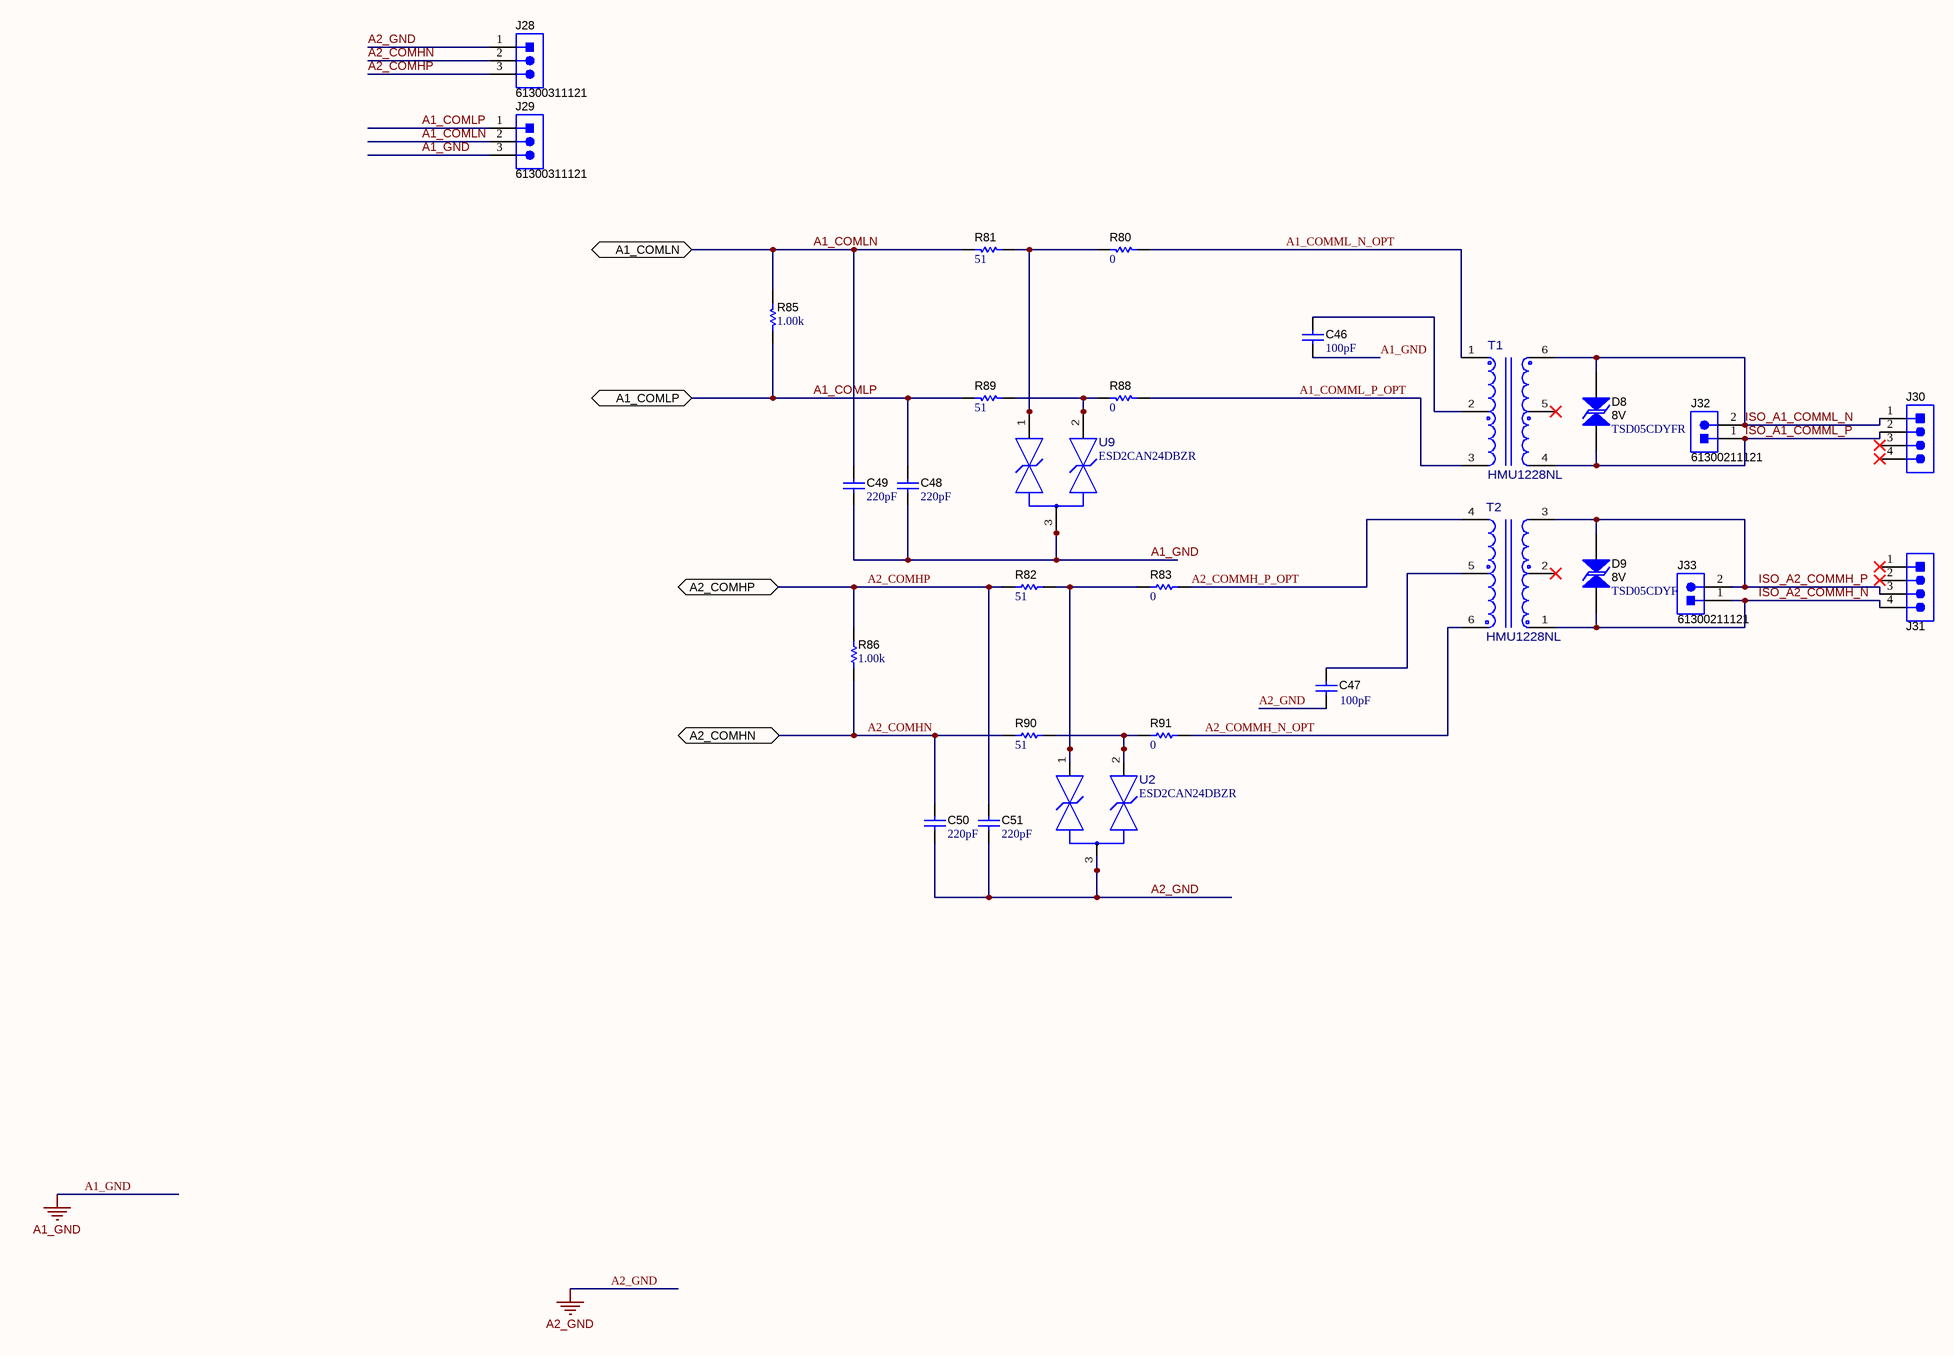
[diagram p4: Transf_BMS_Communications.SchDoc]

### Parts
C46  ValueDisplayed: 100pF  [0603]  (hidden comment: GCM1885C1H101JA16J)
C47  ValueDisplayed: 100pF  [0603]  (hidden comment: GCM1885C1H101JA16J)
C48  Cap_F: 220pF  [0603]  (hidden comment: CL10B221JB8NNNC)
C49  Cap_F: 220pF  [0603]  (hidden comment: CL10B221JB8NNNC)
C50  Cap_F: 220pF  [0603]  (hidden comment: CL10B221JB8NNNC)
C51  Cap_F: 220pF  [0603]  (hidden comment: CL10B221JB8NNNC)
D8  value 8V  PartNumber: TSD05CDYFR  [SOD-323-Bi]  (hidden comment: CDSOD323-T08SC)
D9  value 8V  PartNumber: TSD05CDYFR  [SOD-323-Bi]  (hidden comment: CDSOD323-T08SC)
J28  61300311121  [WURTH_61300311121]
J29  61300311121  [WURTH_61300311121]
J30  70551-0038  [Molex_70551-0038]  (value not drawn)
J31  70551-0038  [Molex_70551-0038]  (value not drawn)
J32  61300211121  [WURTH_61300211121]
J33  61300211121  [WURTH_61300211121]
R80  ValueDisplayed: 0  [0603]  (hidden comment: RC0603JR-070RL)
R81  ValueDisplayed: 51  [0603]  (hidden comment: CRCW060351R0JNEA)
R82  ValueDisplayed: 51  [0603]  (hidden comment: CRCW060351R0JNEA)
R83  ValueDisplayed: 0  [0603]  (hidden comment: RC0603JR-070RL)
R85  ValueDisplayed: 1.00k  [0603]  (hidden comment: ERJ-3EKF1001V)
R86  ValueDisplayed: 1.00k  [0603]  (hidden comment: ERJ-3EKF1001V)
R88  ValueDisplayed: 0  [0603]  (hidden comment: RC0603JR-070RL)
R89  ValueDisplayed: 51  [0603]  (hidden comment: CRCW060351R0JNEA)
R90  ValueDisplayed: 51  [0603]  (hidden comment: CRCW060351R0JNEA)
R91  ValueDisplayed: 0  [0603]  (hidden comment: RC0603JR-070RL)
T1  HMU1228NL  [FP-HMU1228NL_SMT_TRANSFORMER_8MM89_10MM09-MFG]
T2  HMU1228NL  [FP-HMU1228NL_SMT_TRANSFORMER_8MM89_10MM09-MFG]
U2  ESD2CAN24DBZR  [DBZ0003A-MFG]
U9  ESD2CAN24DBZR  [DBZ0003A-MFG]

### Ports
A1_COMLN (bidir), A1_COMLP (bidir), A2_COMHN (bidir), A2_COMHP (bidir)

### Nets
A1_GND: C46.2 C48.2 C49.2 J29.3 U9.3(GND)
A2_GND: C47.2 C50.2 C51.2 J28.1 U2.3(GND)
A1_COMLN: C49.1 J29.2 R81.2 R85.2 ; port A1_COMLN
A1_COMLP: C48.1 J29.1 R85.1 R89.2 ; port A1_COMLP
A1_COMML_N_OPT: R80.1 T1.1(TD+)
A1_COMML_P_OPT: R88.1 T1.3(TD-)
A2_COMHN: C50.1 J28.2 R86.1 R90.1 ; port A2_COMHN
A2_COMHP: C51.1 J28.3 R82.1 R86.2 ; port A2_COMHP
A2_COMMH_N_OPT: R91.2 T2.6(TX+)
A2_COMMH_P_OPT: R83.2 T2.4(TX-)
ISO_A1_COMML_N: D8.2 J30.1 J32.2 T1.6(TX+)
ISO_A1_COMML_P: D8.1 J30.2 J32.1 T1.4(TX-)
ISO_A2_COMMH_N: D9.1 J31.4 J33.1 T2.1(TD+)
ISO_A2_COMMH_P: D9.2 J31.3 J33.2 T2.3(TD-)
NetC46_1: C46.1 T1.2(TCT)
NetC47_1: C47.1 T2.5(CMT)
NetR80_2: R80.2 R81.1 U9.1(1_IO)
NetR82_2: R82.2 R83.1 U2.1(1_IO)
NetR88_2: R88.2 R89.1 U9.2(2_IO)
NetR90_2: R90.2 R91.1 U2.2(2_IO)

Not connected (* = marked no-connect by the designer): J30 3* 4*; J31 1* 2*; T1 5(CMT)*; T2 2(TCT)*

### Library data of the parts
C46 C47 = CMP-0750041-1: CAP, CERM, 100 pF, 50 V,+/- 5%, C0G/NP0, AEC-Q200 Grade 1, 0603; Manufacturer: MuRata; TaMin_C: -55°C; Polarized: N; SizeAreaWB_mm2: 4.68; U/M: EA; Value: 100pF; TaMax_C: 125°C; SizeZ_mm: 1; SizeX_mm: 1.6; SizeY_mm: 0.8; Value2: 50V; SizeArea_mm2: 1.28; AEC Qualified: Y; AEC Category: Q200
C48-C51 = CMP-0860329-1: CAP, CERM, 220 pF, 50 V,+/- 5%, X7R, 0603; Manufacturer: Samsung Electro-Mechanics; TaMin_C: -55°C; Polarized: N; SizeAreaWB_mm2: 4.68; U/M: EA; Value: 220pF; TaMax_C: 125°C; SizeZ_mm: 1; SizeX_mm: 1.6; SizeY_mm: 0.8; Value2: 50V; SizeArea_mm2: 1.28; AEC Category: Q200
D8 D9 = CMP-0065114-2: Diode, TVS, Bi, 8 V, 18.5 Vc, SOD-323; Manufacturer: Texas Instruments; SizeAreaWB_mm2: 8.695; Ppk: 400W; SizeArea_mm2: 3.645; AEC Qualified: N; SizeY_mm: 1.35; Ipp: 17A; Vbr_Min: 8.5V; Vc: 18.5V; SizeZ_mm: 1.0; SizeX_mm: 2.7; AEC Category: Q101
J28 J29 = CMP-0054796-4: Header, 2.54 mm, 3x1, Gold, TH; Manufacturer: Wurth Elektronik; Green_REACh: Passed; CT: FALSE; CNHeader: TRUE; Green_Lifecycle: Active
J30 J31 = CMP-0055239-1: Header(shrouded), 2.54mm, 4x1, R/A, Gold, TH; Manufacturer: Molex; CNHeader: FALSE; Current_A: 3A; Green_Lifecycle: Active; Shrouded: Y; Gender: Male; Green_REACh: Passed; Voltage_V: 250V; Row_Count: 1; Pitch_mm: 2.54
J32 J33 = CMP-0054794-2: Header, 2.54 mm, 2x1, Gold, TH; Manufacturer: Wurth Elektronik; Shrouded: N; Gender: Male; Green_REACh: Passed; Pitch_mm: 2.54; Green_Lifecycle: Active; Row_Count: 1; Cert_UL: Y
R80 R83 R88 R91 = CMP-0025885-5: as R1 on sheet BMU_A2_bq79616
R81 R82 R90 = CMP-0025825-4: RES, 51, 5%, 0.1 W, AEC-Q200 Grade 0, 0603; Manufacturer: Vishay-Dale; Power_W: 100mW; TempCo: 200 ppm/C; Value_Code: 51R0; Value: 51; EIA_Code: E24; SizeX_mm: 1.6; SizeY_mm: 0.8; SizeZ_mm: 1; Value2: 0.1W; SizeArea_mm2: 1.28; AEC Qualified: Y; VDC_V: 75V; AEC Category: Q200; AEC Grade: 0
R85 R86 = CMP-0022680-4: RES, 1.00 k, 1%, 0.1 W, 0603; Manufacturer: Panasonic; Power_W: 100mW; TempCo: 100 ppm/C; Value_Code: 1k00; Value: 1.00k; EIA_Code: E96; Res_ohm: 1k; SizeX_mm: 1.6; SizeY_mm: 0.8; SizeZ_mm: 1; Value2: 0.1W; SizeArea_mm2: 1.28; VDC_V: 75V; AEC Category: Q200; U/M: EA
R89 = CMP-0025825-4: RES, 51, 5%, 0.1 W, AEC-Q200 Grade 0, 0603; Manufacturer: Vishay-Dale; TempCo: 200 ppm/C; Value: 51; SizeX_mm: 1.6; SizeY_mm: 0.8; SizeZ_mm: 1; Value2: 0.1W; SizeArea_mm2: 1.28; AEC Qualified: Y; VDC_V: 75V; AEC Category: Q200; AEC Grade: 0; Power_W: 100mW; Value_Code: 51R0; EIA_Code: E24
T1 T2 = CMP-0086619-1: BMS TRANSFORMER; Manufacturer: Pulse; Ns1toNp: 1:1; Ind_H: 150µH; SizeZ_mm: 6.85mm; AEC Grade: Grade 1; AEC Qualified: Yes
U2 U9 = CMP-0093261-1: 24-V, 2-Channel ESD Protection Diode for In-Vehicle Networks; Manufacturer: Texas Instruments; Cap_F: 3pF; Breakdown Voltage: 25.5V; Clamping Voltage: 32V; TaMax_C: +150°C; Direction: Bidirectional; TaMin_C: -55°C; Ipp: 3.5A; VRWM: 24V; Standoff Height: 0.01mm; SizeZ_mm: 1.12mm; Ppk: 147W; AEC Qualified: No; Number Of Channels: 2

## Sheet Cap_BMS_Communications.SchDoc
size C; SheetNumber: 4; SheetTotal: 9
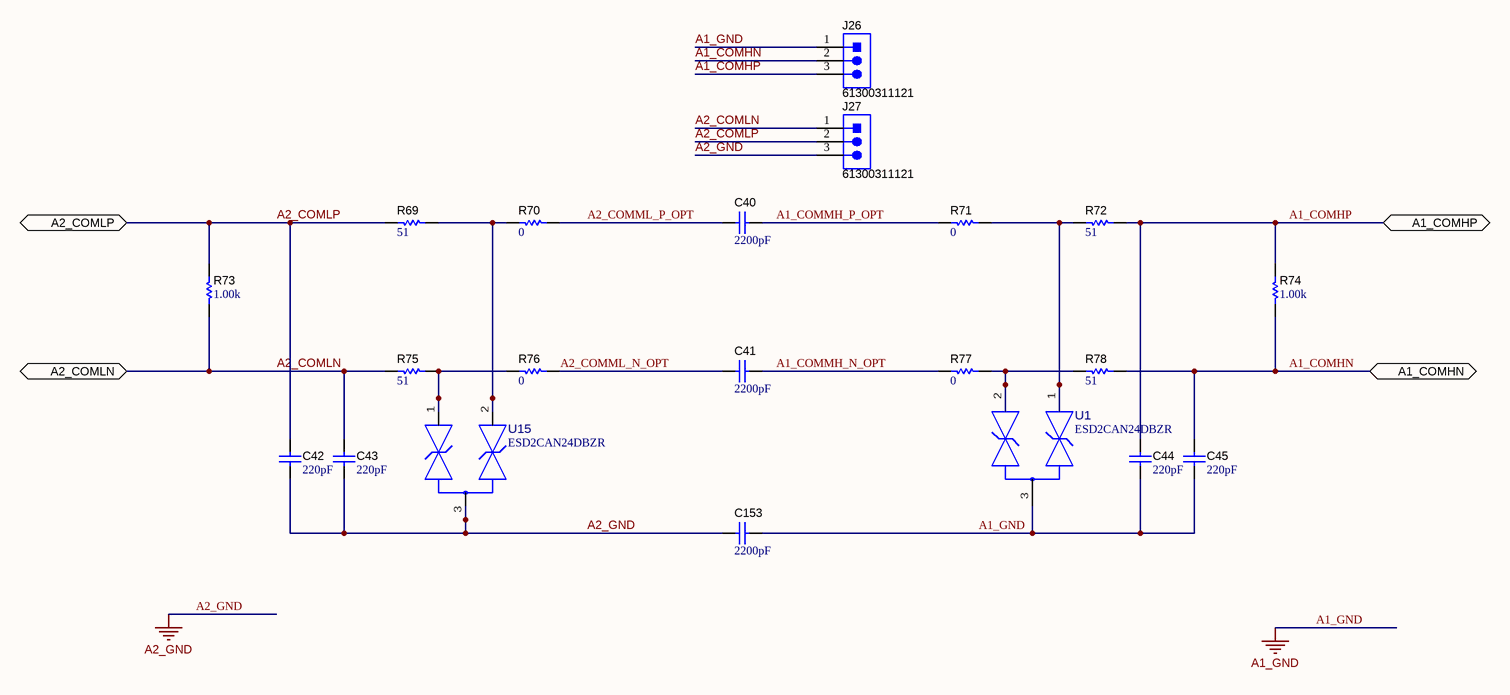
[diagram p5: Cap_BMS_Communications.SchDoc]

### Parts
C40  ValueDisplayed: 2200pF  [1206_180]  (hidden comment: 1206J2K00222KXR)
C41  ValueDisplayed: 2200pF  [1206_180]  (hidden comment: 1206J2K00222KXR)
C42  Cap_F: 220pF  [0603]  (hidden comment: CL10B221JB8NNNC)
C43  Cap_F: 220pF  [0603]  (hidden comment: CL10B221JB8NNNC)
C44  Cap_F: 220pF  [0603]  (hidden comment: CL10B221JB8NNNC)
C45  Cap_F: 220pF  [0603]  (hidden comment: CL10B221JB8NNNC)
C153  ValueDisplayed: 2200pF  [1206_180]  (hidden comment: 1206J2K00222KXR)
J26  61300311121  [WURTH_61300311121]
J27  61300311121  [WURTH_61300311121]
R69  ValueDisplayed: 51  [0603]  (hidden comment: CRCW060351R0JNEA)
R70  ValueDisplayed: 0  [0603]  (hidden comment: RC0603JR-070RL)
R71  ValueDisplayed: 0  [0603]  (hidden comment: RC0603JR-070RL)
R72  ValueDisplayed: 51  [0603]  (hidden comment: CRCW060351R0JNEA)
R73  ValueDisplayed: 1.00k  [0603]  (hidden comment: ERJ-3EKF1001V)
R74  ValueDisplayed: 1.00k  [0603]  (hidden comment: ERJ-3EKF1001V)
R75  ValueDisplayed: 51  [0603]  (hidden comment: CRCW060351R0JNEA)
R76  ValueDisplayed: 0  [0603]  (hidden comment: RC0603JR-070RL)
R77  ValueDisplayed: 0  [0603]  (hidden comment: RC0603JR-070RL)
R78  ValueDisplayed: 51  [0603]  (hidden comment: CRCW060351R0JNEA)
U1  ESD2CAN24DBZR  [DBZ0003A-MFG]
U15  ESD2CAN24DBZR  [DBZ0003A-MFG]

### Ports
A1_COMHN (bidir), A1_COMHP (bidir), A2_COMLN (bidir), A2_COMLP (bidir)

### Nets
A1_GND: C44.2 C45.2 C153.2 J26.1 U1.3(GND)
A2_GND: C42.2 C43.2 C153.1 J27.3 U15.3(GND)
A1_COMHN: C45.1 J26.2 R74.1 R78.1 ; port A1_COMHN
A1_COMHP: C44.1 J26.3 R72.1 R74.2 ; port A1_COMHP
A1_COMMH_N_OPT: C41.2 R77.2
A1_COMMH_P_OPT: C40.2 R71.2
A2_COMLN: C43.1 J27.1 R73.1 R75.2 ; port A2_COMLN
A2_COMLP: C42.1 J27.2 R69.2 R73.2 ; port A2_COMLP
A2_COMML_N_OPT: C41.1 R76.1
A2_COMML_P_OPT: C40.1 R70.1
NetR69_1: R69.1 R70.2 U15.2(2_IO)
NetR71_1: R71.1 R72.2 U1.1(1_IO)
NetR75_1: R75.1 R76.2 U15.1(1_IO)
NetR77_1: R77.1 R78.2 U1.2(2_IO)

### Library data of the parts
C40 C41 C153 = CMP-0077201-1: CAP, CERM, 2200 pF, 2000 V,+/- 10%, X7R, AEC-Q200 Grade 1, 1206; Manufacturer: Knowles Capacitors; TaMin_C: -55°C; Polarized: N; SizeAreaWB_mm2: 10.92; U/M: EA; Value: 2200pF; TaMax_C: 125°C; SizeZ_mm: 1.8; SizeX_mm: 3.2; SizeY_mm: 1.6; Cap_Case: 1206; Value2: 2000V; SizeArea_mm2: 5.12; AEC Qualified: Y; Cap_F: 2.2nF; VDC_V: 2kV; AEC Grade: 1; AEC Category: Q200
C42-C45 = CMP-0860329-1: as C48 on sheet Transf_BMS_Communications
J26 J27 = CMP-0054796-4: as J28 on sheet Transf_BMS_Communications
R69 R72 R78 = CMP-0025825-4: as R81 on sheet Transf_BMS_Communications
R70 R71 R76 R77 = CMP-0025885-5: as R1 on sheet BMU_A2_bq79616
R73 R74 = CMP-0022680-4: as R85 on sheet Transf_BMS_Communications
R75 = CMP-0025825-4: as R89 on sheet Transf_BMS_Communications
U1 U15 = CMP-0093261-1: as U2 on sheet Transf_BMS_Communications

## Sheet BMU_A1_Cell_Network.SchDoc
size 558 x 431 mm; Date: Not shown in title block; ApprovedBy: Not shown in title block; CheckedBy: Not shown in title block; Author: Not shown in title block; CompanyName: Not shown in title block; Engineer: Not shown in title block; Organization: Not shown in title block; Address1: Not shown in title block; Address2: Not shown in title block; Address3: Not shown in title block; Address4: Not shown in title block; DocumentNumber: 1; Revision: Use project parameter SCH_Rev; SheetNumber: 8; SheetTotal: 9; PageSetup: Record=PageOptions¦CenterHorizontal=True¦CenterVertical=True¦PrintScale=1.00¦XCorrection=1.00¦YCorrection=1.00¦PrintKind=0¦BorderSize=5000000¦LeftOffset=0¦BottomOffset=0¦Orientation=2¦PaperLength=1000¦PaperWidth=1000¦Scale=100¦PaperSource=15¦PrintQuality=600¦MediaType=1¦DitherType=10¦PaperKind=Letter¦PrintScaleMode=1
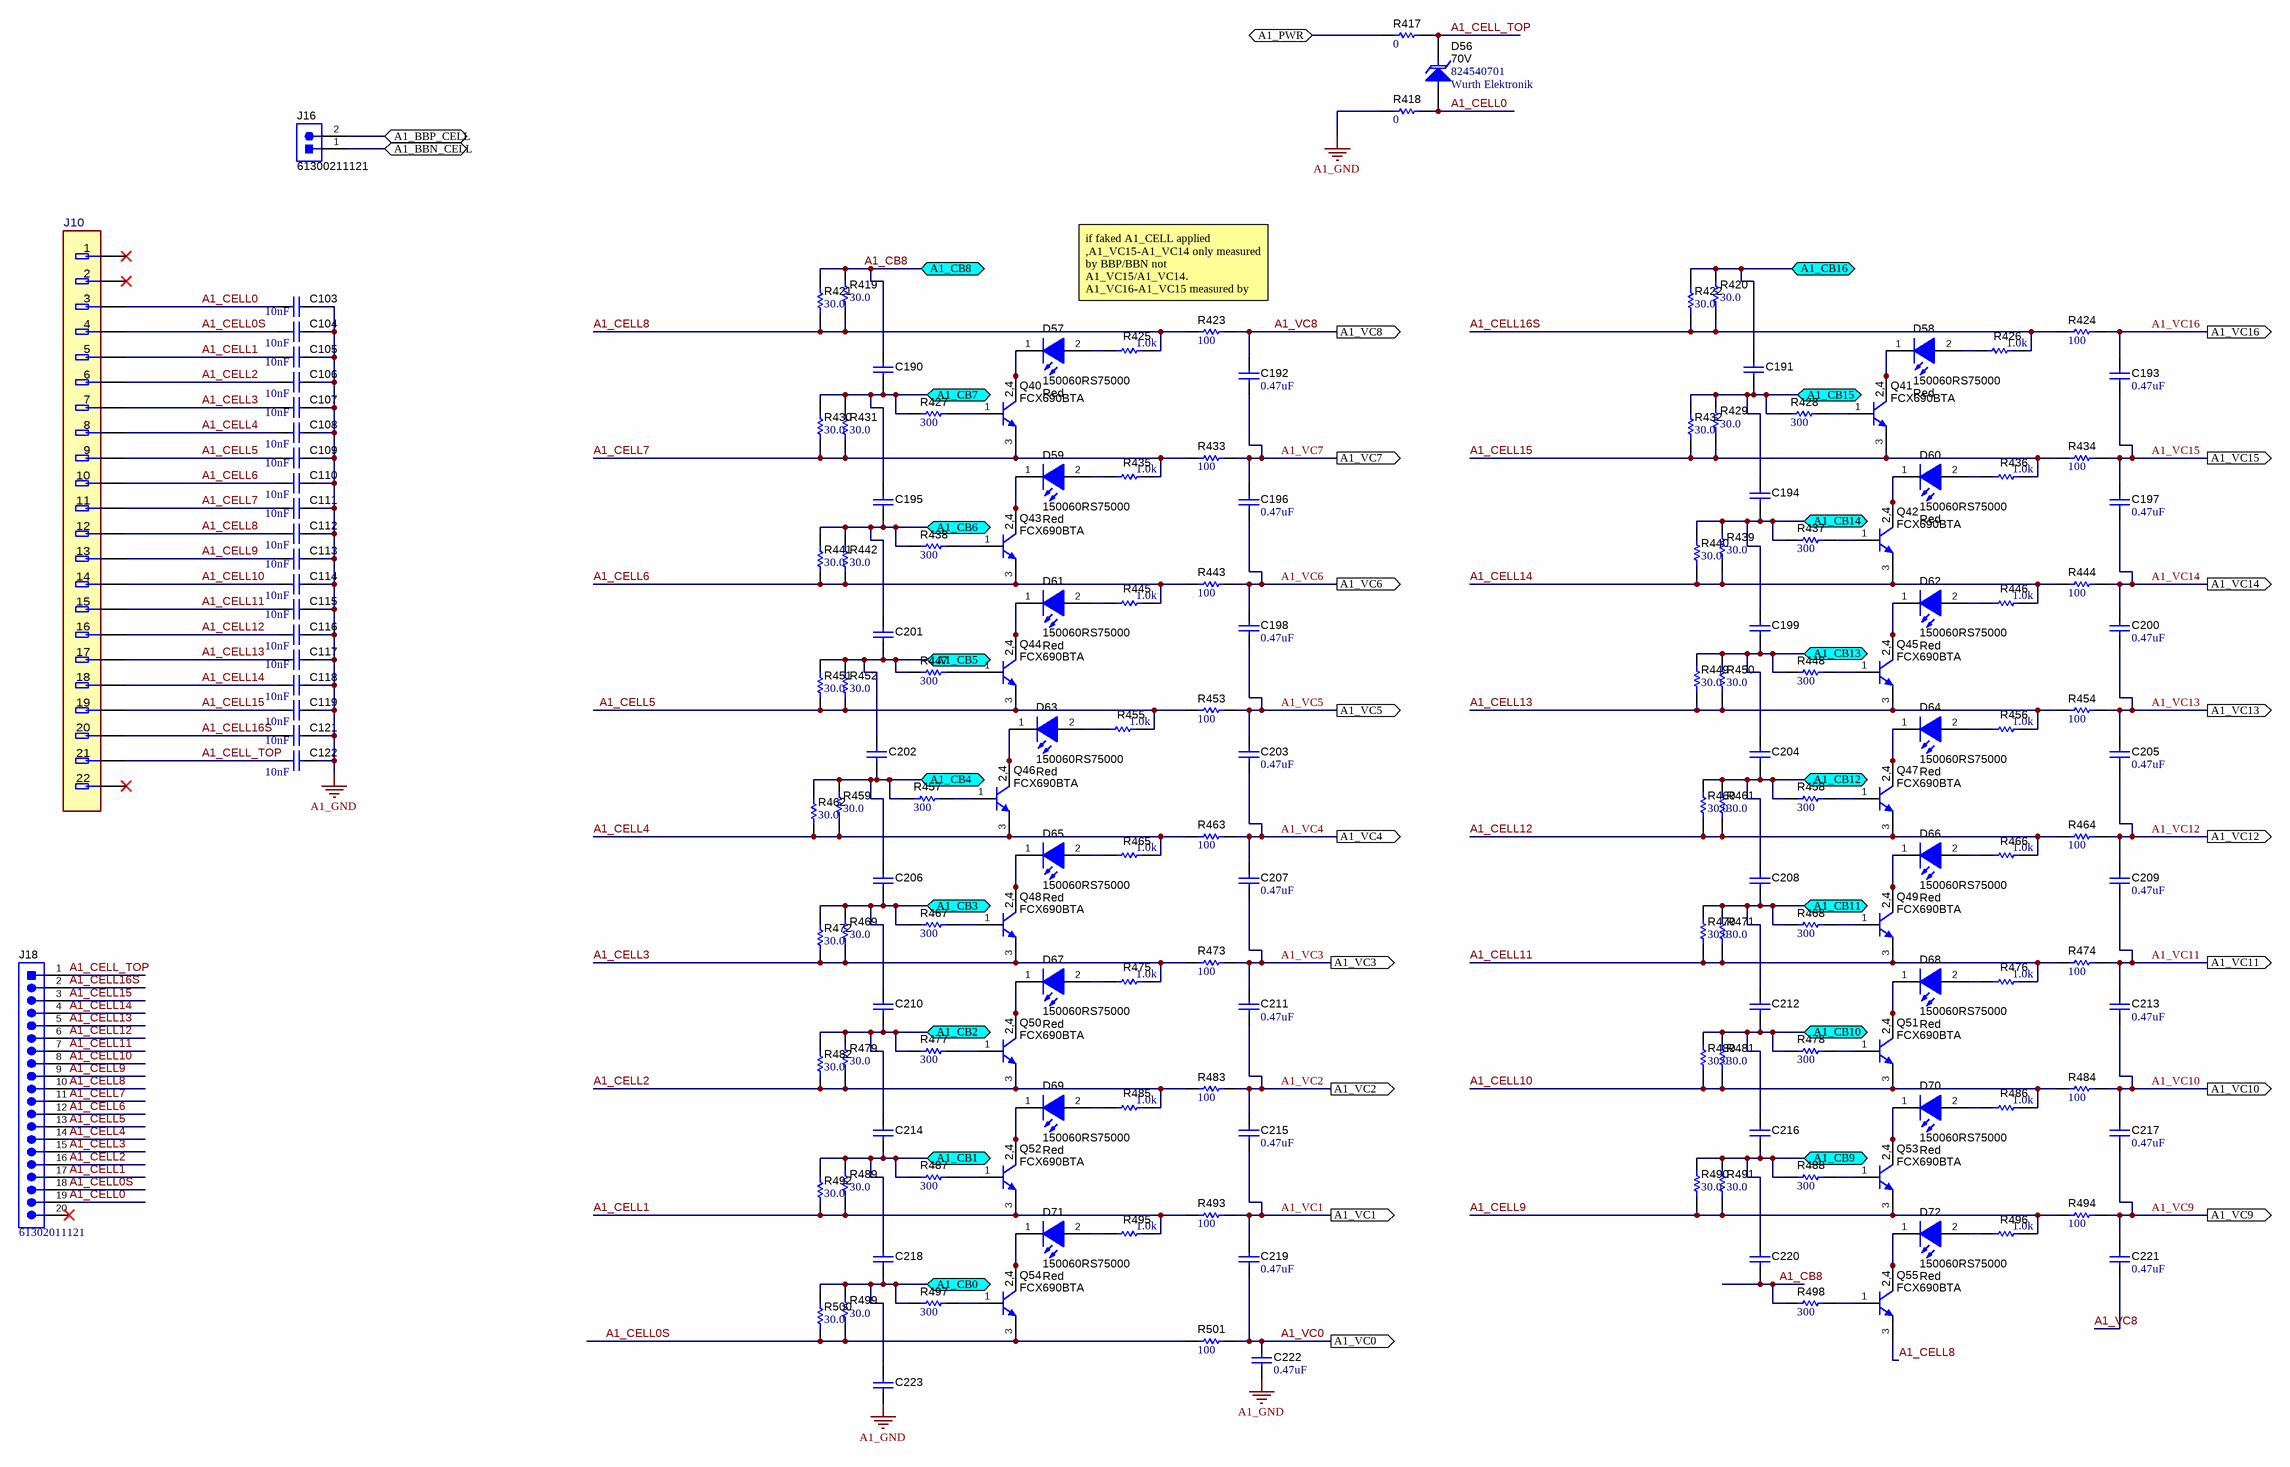
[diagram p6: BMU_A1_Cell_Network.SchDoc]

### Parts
C103  Cap_F: 10nF  [0603]  (hidden comment: 885012206114)
C104  Cap_F: 10nF  [0603]  (hidden comment: 885012206114)
C105  Cap_F: 10nF  [0603]  (hidden comment: 885012206114)
C106  Cap_F: 10nF  [0603]  (hidden comment: 885012206114)
C107  Cap_F: 10nF  [0603]  (hidden comment: 885012206114)
C108  Cap_F: 10nF  [0603]  (hidden comment: 885012206114)
C109  Cap_F: 10nF  [0603]  (hidden comment: 885012206114)
C110  Cap_F: 10nF  [0603]  (hidden comment: 885012206114)
C111  Cap_F: 10nF  [0603]  (hidden comment: 885012206114)
C112  Cap_F: 10nF  [0603]  (hidden comment: 885012206114)
C113  Cap_F: 10nF  [0603]  (hidden comment: 885012206114)
C114  Cap_F: 10nF  [0603]  (hidden comment: 885012206114)
C115  Cap_F: 10nF  [0603]  (hidden comment: 885012206114)
C116  Cap_F: 10nF  [0603]  (hidden comment: 885012206114)
C117  Cap_F: 10nF  [0603]  (hidden comment: 885012206114)
C118  Cap_F: 10nF  [0603]  (hidden comment: 885012206114)
C119  Cap_F: 10nF  [0603]  (hidden comment: 885012206114)
C121  Cap_F: 10nF  [0603]  (hidden comment: 885012206114)
C122  Cap_F: 10nF  [0603]  (hidden comment: 885012206114)
C190  GCM188R71C474KA55D  [0603]  (value not drawn)
C191  GCM188R71C474KA55D  [0603]  (value not drawn)
C192  ValueDisplayed: 0.47uF  [0603]  (hidden comment: GCM188R71C474KA55D)
C193  ValueDisplayed: 0.47uF  [0603]  (hidden comment: GCM188R71C474KA55D)
C194  GCM188R71C474KA55D  [0603]  (value not drawn)
C195  GCM188R71C474KA55D  [0603]  (value not drawn)
C196  ValueDisplayed: 0.47uF  [0603]  (hidden comment: GCM188R71C474KA55D)
C197  ValueDisplayed: 0.47uF  [0603]  (hidden comment: GCM188R71C474KA55D)
C198  ValueDisplayed: 0.47uF  [0603]  (hidden comment: GCM188R71C474KA55D)
C199  GCM188R71C474KA55D  [0603]  (value not drawn)
C200  ValueDisplayed: 0.47uF  [0603]  (hidden comment: GCM188R71C474KA55D)
C201  GCM188R71C474KA55D  [0603]  (value not drawn)
C202  GCM188R71C474KA55D  [0603]  (value not drawn)
C203  ValueDisplayed: 0.47uF  [0603]  (hidden comment: GCM188R71C474KA55D)
C204  GCM188R71C474KA55D  [0603]  (value not drawn)
C205  ValueDisplayed: 0.47uF  [0603]  (hidden comment: GCM188R71C474KA55D)
C206  GCM188R71C474KA55D  [0603]  (value not drawn)
C207  ValueDisplayed: 0.47uF  [0603]  (hidden comment: GCM188R71C474KA55D)
C208  GCM188R71C474KA55D  [0603]  (value not drawn)
C209  ValueDisplayed: 0.47uF  [0603]  (hidden comment: GCM188R71C474KA55D)
C210  GCM188R71C474KA55D  [0603]  (value not drawn)
C211  ValueDisplayed: 0.47uF  [0603]  (hidden comment: GCM188R71C474KA55D)
C212  GCM188R71C474KA55D  [0603]  (value not drawn)
C213  ValueDisplayed: 0.47uF  [0603]  (hidden comment: GCM188R71C474KA55D)
C214  GCM188R71C474KA55D  [0603]  (value not drawn)
C215  ValueDisplayed: 0.47uF  [0603]  (hidden comment: GCM188R71C474KA55D)
C216  GCM188R71C474KA55D  [0603]  (value not drawn)
C217  ValueDisplayed: 0.47uF  [0603]  (hidden comment: GCM188R71C474KA55D)
C218  GCM188R71C474KA55D  [0603]  (value not drawn)
C219  ValueDisplayed: 0.47uF  [0603]  (hidden comment: GCM188R71C474KA55D)
C220  GCM188R71C474KA55D  [0603]  (value not drawn)
C221  ValueDisplayed: 0.47uF  [0603]  (hidden comment: GCM188R71C474KA55D)
C222  ValueDisplayed: 0.47uF  [0603]  (hidden comment: GCM188R71C474KA55D)
C223  GCM188R71C474KA55D  [0603]  (value not drawn)
D56  value 70V  PartNumber: 824540701  Manufacturer: Wurth Elektronik  [SMC_265]  (hidden comment: SMCJ70A)
D57  150060RS75000  value Red  [WL-SMCW_RED]
D58  150060RS75000  value Red  [WL-SMCW_RED]
D59  150060RS75000  value Red  [WL-SMCW_RED]
D60  150060RS75000  value Red  [WL-SMCW_RED]
D61  150060RS75000  value Red  [WL-SMCW_RED]
D62  150060RS75000  value Red  [WL-SMCW_RED]
D63  150060RS75000  value Red  [WL-SMCW_RED]
D64  150060RS75000  value Red  [WL-SMCW_RED]
D65  150060RS75000  value Red  [WL-SMCW_RED]
D66  150060RS75000  value Red  [WL-SMCW_RED]
D67  150060RS75000  value Red  [WL-SMCW_RED]
D68  150060RS75000  value Red  [WL-SMCW_RED]
D69  150060RS75000  value Red  [WL-SMCW_RED]
D70  150060RS75000  value Red  [WL-SMCW_RED]
D71  150060RS75000  value Red  [WL-SMCW_RED]
D72  150060RS75000  value Red  [WL-SMCW_RED]
J10  705550056  [FP-705550056_HDR22-MFG]  (value not drawn)
J16  61300211121  [WURTH_61300211121]
J18  PartNumber: 61302011121  [TSW-120-07-G-S]  (hidden comment: TSW-120-07-G-S)
Q40  FCX690BTA  [SOT-89-3]
Q41  FCX690BTA  [SOT-89-3]
Q42  FCX690BTA  [SOT-89-3]
Q43  FCX690BTA  [SOT-89-3]
Q44  FCX690BTA  [SOT-89-3]
Q45  FCX690BTA  [SOT-89-3]
Q46  FCX690BTA  [SOT-89-3]
Q47  FCX690BTA  [SOT-89-3]
Q48  FCX690BTA  [SOT-89-3]
Q49  FCX690BTA  [SOT-89-3]
Q50  FCX690BTA  [SOT-89-3]
Q51  FCX690BTA  [SOT-89-3]
Q52  FCX690BTA  [SOT-89-3]
Q53  FCX690BTA  [SOT-89-3]
Q54  FCX690BTA  [SOT-89-3]
Q55  FCX690BTA  [SOT-89-3]
R417  ValueDisplayed: 0  [0603]  (hidden comment: CRCW06030000Z0EA)
R418  ValueDisplayed: 0  [0603]  (hidden comment: CRCW06030000Z0EA)
R419  ValueDisplayed: 30.0  [1210]  (hidden comment: RC1210FR-0730RL)
R420  ValueDisplayed: 30.0  [1210]  (hidden comment: RC1210FR-0730RL)
R421  ValueDisplayed: 30.0  [1210]  (hidden comment: RC1210FR-0730RL)
R422  ValueDisplayed: 30.0  [1210]  (hidden comment: RC1210FR-0730RL)
R423  ValueDisplayed: 100  [0603]  (hidden comment: ERA-3AEB101V)
R424  ValueDisplayed: 100  [0603]  (hidden comment: ERA-3AEB101V)
R425  ValueDisplayed: 1.0k  [0603]  (hidden comment: CRCW06031K00JNEA)
R426  ValueDisplayed: 1.0k  [0603]  (hidden comment: CRCW06031K00JNEA)
R427  ValueDisplayed: 300  [0402]  (hidden comment: CRCW0402300RJNED)
R428  ValueDisplayed: 300  [0402]  (hidden comment: CRCW0402300RJNED)
R429  ValueDisplayed: 30.0  [1210]  (hidden comment: RC1210FR-0730RL)
R430  ValueDisplayed: 30.0  [1210]  (hidden comment: RC1210FR-0730RL)
R431  ValueDisplayed: 30.0  [1210]  (hidden comment: RC1210FR-0730RL)
R432  ValueDisplayed: 30.0  [1210]  (hidden comment: RC1210FR-0730RL)
R433  ValueDisplayed: 100  [0603]  (hidden comment: ERA-3AEB101V)
R434  ValueDisplayed: 100  [0603]  (hidden comment: ERA-3AEB101V)
R435  ValueDisplayed: 1.0k  [0603]  (hidden comment: CRCW06031K00JNEA)
R436  ValueDisplayed: 1.0k  [0603]  (hidden comment: CRCW06031K00JNEA)
R437  ValueDisplayed: 300  [0402]  (hidden comment: CRCW0402300RJNED)
R438  ValueDisplayed: 300  [0402]  (hidden comment: CRCW0402300RJNED)
R439  ValueDisplayed: 30.0  [1210]  (hidden comment: RC1210FR-0730RL)
R440  ValueDisplayed: 30.0  [1210]  (hidden comment: RC1210FR-0730RL)
R441  ValueDisplayed: 30.0  [1210]  (hidden comment: RC1210FR-0730RL)
R442  ValueDisplayed: 30.0  [1210]  (hidden comment: RC1210FR-0730RL)
R443  ValueDisplayed: 100  [0603]  (hidden comment: ERA-3AEB101V)
R444  ValueDisplayed: 100  [0603]  (hidden comment: ERA-3AEB101V)
R445  ValueDisplayed: 1.0k  [0603]  (hidden comment: CRCW06031K00JNEA)
R446  ValueDisplayed: 1.0k  [0603]  (hidden comment: CRCW06031K00JNEA)
R447  ValueDisplayed: 300  [0402]  (hidden comment: CRCW0402300RJNED)
R448  ValueDisplayed: 300  [0402]  (hidden comment: CRCW0402300RJNED)
R449  ValueDisplayed: 30.0  [1210]  (hidden comment: RC1210FR-0730RL)
R450  ValueDisplayed: 30.0  [1210]  (hidden comment: RC1210FR-0730RL)
R451  ValueDisplayed: 30.0  [1210]  (hidden comment: RC1210FR-0730RL)
R452  ValueDisplayed: 30.0  [1210]  (hidden comment: RC1210FR-0730RL)
R453  ValueDisplayed: 100  [0603]  (hidden comment: ERA-3AEB101V)
R454  ValueDisplayed: 100  [0603]  (hidden comment: ERA-3AEB101V)
R455  ValueDisplayed: 1.0k  [0603]  (hidden comment: CRCW06031K00JNEA)
R456  ValueDisplayed: 1.0k  [0603]  (hidden comment: CRCW06031K00JNEA)
R457  ValueDisplayed: 300  [0402]  (hidden comment: CRCW0402300RJNED)
R458  ValueDisplayed: 300  [0402]  (hidden comment: CRCW0402300RJNED)
R459  ValueDisplayed: 30.0  [1210]  (hidden comment: RC1210FR-0730RL)
R460  ValueDisplayed: 30.0  [1210]  (hidden comment: RC1210FR-0730RL)
R461  ValueDisplayed: 30.0  [1210]  (hidden comment: RC1210FR-0730RL)
R462  ValueDisplayed: 30.0  [1210]  (hidden comment: RC1210FR-0730RL)
R463  ValueDisplayed: 100  [0603]  (hidden comment: ERA-3AEB101V)
R464  ValueDisplayed: 100  [0603]  (hidden comment: ERA-3AEB101V)
R465  ValueDisplayed: 1.0k  [0603]  (hidden comment: CRCW06031K00JNEA)
R466  ValueDisplayed: 1.0k  [0603]  (hidden comment: CRCW06031K00JNEA)
R467  ValueDisplayed: 300  [0402]  (hidden comment: CRCW0402300RJNED)
R468  ValueDisplayed: 300  [0402]  (hidden comment: CRCW0402300RJNED)
R469  ValueDisplayed: 30.0  [1210]  (hidden comment: RC1210FR-0730RL)
R470  ValueDisplayed: 30.0  [1210]  (hidden comment: RC1210FR-0730RL)
R471  ValueDisplayed: 30.0  [1210]  (hidden comment: RC1210FR-0730RL)
R472  ValueDisplayed: 30.0  [1210]  (hidden comment: RC1210FR-0730RL)
R473  ValueDisplayed: 100  [0603]  (hidden comment: ERA-3AEB101V)
R474  ValueDisplayed: 100  [0603]  (hidden comment: ERA-3AEB101V)
R475  ValueDisplayed: 1.0k  [0603]  (hidden comment: CRCW06031K00JNEA)
R476  ValueDisplayed: 1.0k  [0603]  (hidden comment: CRCW06031K00JNEA)
R477  ValueDisplayed: 300  [0402]  (hidden comment: CRCW0402300RJNED)
R478  ValueDisplayed: 300  [0402]  (hidden comment: CRCW0402300RJNED)
R479  ValueDisplayed: 30.0  [1210]  (hidden comment: RC1210FR-0730RL)
R480  ValueDisplayed: 30.0  [1210]  (hidden comment: RC1210FR-0730RL)
R481  ValueDisplayed: 30.0  [1210]  (hidden comment: RC1210FR-0730RL)
R482  ValueDisplayed: 30.0  [1210]  (hidden comment: RC1210FR-0730RL)
R483  ValueDisplayed: 100  [0603]  (hidden comment: ERA-3AEB101V)
R484  ValueDisplayed: 100  [0603]  (hidden comment: ERA-3AEB101V)
R485  ValueDisplayed: 1.0k  [0603]  (hidden comment: CRCW06031K00JNEA)
R486  ValueDisplayed: 1.0k  [0603]  (hidden comment: CRCW06031K00JNEA)
R487  ValueDisplayed: 300  [0402]  (hidden comment: CRCW0402300RJNED)
R488  ValueDisplayed: 300  [0402]  (hidden comment: CRCW0402300RJNED)
R489  ValueDisplayed: 30.0  [1210]  (hidden comment: RC1210FR-0730RL)
R490  ValueDisplayed: 30.0  [1210]  (hidden comment: RC1210FR-0730RL)
R491  ValueDisplayed: 30.0  [1210]  (hidden comment: RC1210FR-0730RL)
R492  ValueDisplayed: 30.0  [1210]  (hidden comment: RC1210FR-0730RL)
R493  ValueDisplayed: 100  [0603]  (hidden comment: ERA-3AEB101V)
R494  ValueDisplayed: 100  [0603]  (hidden comment: ERA-3AEB101V)
R495  ValueDisplayed: 1.0k  [0603]  (hidden comment: CRCW06031K00JNEA)
R496  ValueDisplayed: 1.0k  [0603]  (hidden comment: CRCW06031K00JNEA)
R497  ValueDisplayed: 300  [0402]  (hidden comment: CRCW0402300RJNED)
R498  ValueDisplayed: 300  [0402]  (hidden comment: CRCW0402300RJNED)
R499  ValueDisplayed: 30.0  [1210]  (hidden comment: RC1210FR-0730RL)
R500  ValueDisplayed: 30.0  [1210]  (hidden comment: RC1210FR-0730RL)
R501  ValueDisplayed: 100  [0603]  (hidden comment: ERA-3AEB101V)

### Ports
A1_BBN_CELL (bidir), A1_BBP_CELL (bidir), A1_CB0 (bidir), A1_CB1 (bidir), A1_CB2 (bidir), A1_CB3 (bidir), A1_CB4 (bidir), A1_CB5 (bidir), A1_CB6 (bidir), A1_CB7 (bidir), A1_CB8 (bidir), A1_CB9 (bidir), A1_CB10 (bidir), A1_CB11 (bidir), A1_CB12 (bidir), A1_CB13 (bidir), A1_CB14 (bidir), A1_CB15 (bidir), A1_CB16 (bidir), A1_PWR (bidir), A1_VC0 (out), A1_VC1 (out), A1_VC2 (out), A1_VC3 (out), A1_VC4 (out), A1_VC5 (out), A1_VC6 (out), A1_VC7 (out), A1_VC8 (out), A1_VC9 (out), A1_VC10 (out), A1_VC11 (out), A1_VC12 (out), A1_VC13 (out), A1_VC14 (out), A1_VC15 (out), A1_VC16 (out)

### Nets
A1_GND: C103.2 C104.2 C105.2 C106.2 C107.2 C108.2 C109.2 C110.2 C111.2 C112.2 C113.2 C114.2 C115.2 C116.2 C117.2 C118.2 C119.2 C121.2 C122.2 C222.2 C223.2 R418.1
A1_BBN_CELL: J16.1 ; port A1_BBN_CELL
A1_BBP_CELL: J16.2 ; port A1_BBP_CELL
A1_CB0: C218.2 C223.1 R497.1 R499.2 R500.2 ; port A1_CB0
A1_CB1: C214.2 C218.1 R487.1 R489.2 R492.2 ; port A1_CB1
A1_CB2: C210.2 C214.1 R477.1 R479.2 R482.2 ; port A1_CB2
A1_CB3: C206.2 C210.1 R467.1 R469.2 R472.2 ; port A1_CB3
A1_CB4: C202.2 C206.1 R457.1 R459.2 R462.2 ; port A1_CB4
A1_CB5: C201.2 C202.1 R447.1 R451.2 R452.2 ; port A1_CB5
A1_CB6: C195.2 C201.1 R438.1 R441.2 R442.2 ; port A1_CB6
A1_CB7: C190.2 C195.1 R427.1 R430.2 R431.2 ; port A1_CB7
A1_CB8: C190.1 C220.2 R419.2 R421.2 R498.1 ; port A1_CB8
A1_CB9: C216.2 C220.1 R488.1 R490.2 R491.2 ; port A1_CB9
A1_CB10: C212.2 C216.1 R478.1 R480.2 R481.2 ; port A1_CB10
A1_CB11: C208.2 C212.1 R468.1 R470.2 R471.2 ; port A1_CB11
A1_CB12: C204.2 C208.1 R458.1 R460.2 R461.2 ; port A1_CB12
A1_CB13: C199.2 C204.1 R448.1 R449.2 R450.2 ; port A1_CB13
A1_CB14: C194.2 C199.1 R437.1 R439.2 R440.2 ; port A1_CB14
A1_CB15: C191.2 C194.1 R428.1 R429.2 R432.2 ; port A1_CB15
A1_CB16: C191.1 R420.2 R422.2 ; port A1_CB16
A1_CELL0: C103.1 D56.2(A) J10.3 J18.19 R418.2
A1_CELL0S: C104.1 J10.4 J18.18 Q54.3(E) R499.1 R500.1 R501.1
A1_CELL1: C105.1 J10.5 J18.17 Q52.3(E) R489.1 R492.1 R493.1 R495.1
A1_CELL2: C106.1 J10.6 J18.16 Q50.3(E) R479.1 R482.1 R483.1 R485.1
A1_CELL3: C107.1 J10.7 J18.15 Q48.3(E) R469.1 R472.1 R473.1 R475.1
A1_CELL4: C108.1 J10.8 J18.14 Q46.3(E) R459.1 R462.1 R463.1 R465.1
A1_CELL5: C109.1 J10.9 J18.13 Q44.3(E) R451.1 R452.1 R453.1 R455.1
A1_CELL6: C110.1 J10.10 J18.12 Q43.3(E) R441.1 R442.1 R443.1 R445.1
A1_CELL7: C111.1 J10.11 J18.11 Q40.3(E) R430.1 R431.1 R433.1 R435.1
A1_CELL8: C112.1 J10.12 J18.10 Q55.3(E) R419.1 R421.1 R423.1 R425.1
A1_CELL9: C113.1 J10.13 J18.9 Q53.3(E) R490.1 R491.1 R494.1 R496.1
A1_CELL10: C114.1 J10.14 J18.8 Q51.3(E) R480.1 R481.1 R484.1 R486.1
A1_CELL11: C115.1 J10.15 J18.7 Q49.3(E) R470.1 R471.1 R474.1 R476.1
A1_CELL12: C116.1 J10.16 J18.6 Q47.3(E) R460.1 R461.1 R464.1 R466.1
A1_CELL13: C117.1 J10.17 J18.5 Q45.3(E) R449.1 R450.1 R454.1 R456.1
A1_CELL14: C118.1 J10.18 J18.4 Q42.3(E) R439.1 R440.1 R444.1 R446.1
A1_CELL15: C119.1 J10.19 J18.3 Q41.3(E) R429.1 R432.1 R434.1 R436.1
A1_CELL16S: C121.1 J10.20 J18.2 R420.1 R422.1 R424.1 R426.1
A1_CELL_TOP: C122.1 D56.1(K) J10.21 J18.1 R417.2
A1_PWR: R417.1 ; port A1_PWR
A1_VC0: C219.2 C222.1 R501.2 ; port A1_VC0
A1_VC1: C215.2 C219.1 R493.2 ; port A1_VC1
A1_VC2: C211.2 C215.1 R483.2 ; port A1_VC2
A1_VC3: C207.2 C211.1 R473.2 ; port A1_VC3
A1_VC4: C203.2 C207.1 R463.2 ; port A1_VC4
A1_VC5: C198.2 C203.1 R453.2 ; port A1_VC5
A1_VC6: C196.2 C198.1 R443.2 ; port A1_VC6
A1_VC7: C192.2 C196.1 R433.2 ; port A1_VC7
A1_VC8: C192.1 C221.2 R423.2 ; port A1_VC8
A1_VC9: C217.2 C221.1 R494.2 ; port A1_VC9
A1_VC10: C213.2 C217.1 R484.2 ; port A1_VC10
A1_VC11: C209.2 C213.1 R474.2 ; port A1_VC11
A1_VC12: C205.2 C209.1 R464.2 ; port A1_VC12
A1_VC13: C200.2 C205.1 R454.2 ; port A1_VC13
A1_VC14: C197.2 C200.1 R444.2 ; port A1_VC14
A1_VC15: C193.2 C197.1 R434.2 ; port A1_VC15
A1_VC16: C193.1 R424.2 ; port A1_VC16
NetD57_1: D57.1(K) Q40.2(C) Q40.4(C)
NetD57_2: D57.2(A) R425.2
NetD58_1: D58.1(K) Q41.2(C) Q41.4(C)
NetD58_2: D58.2(A) R426.2
NetD59_1: D59.1(K) Q43.2(C) Q43.4(C)
NetD59_2: D59.2(A) R435.2
NetD60_1: D60.1(K) Q42.2(C) Q42.4(C)
NetD60_2: D60.2(A) R436.2
NetD61_1: D61.1(K) Q44.2(C) Q44.4(C)
NetD61_2: D61.2(A) R445.2
NetD62_1: D62.1(K) Q45.2(C) Q45.4(C)
NetD62_2: D62.2(A) R446.2
NetD63_1: D63.1(K) Q46.2(C) Q46.4(C)
NetD63_2: D63.2(A) R455.2
NetD64_1: D64.1(K) Q47.2(C) Q47.4(C)
NetD64_2: D64.2(A) R456.2
NetD65_1: D65.1(K) Q48.2(C) Q48.4(C)
NetD65_2: D65.2(A) R465.2
NetD66_1: D66.1(K) Q49.2(C) Q49.4(C)
NetD66_2: D66.2(A) R466.2
NetD67_1: D67.1(K) Q50.2(C) Q50.4(C)
NetD67_2: D67.2(A) R475.2
NetD68_1: D68.1(K) Q51.2(C) Q51.4(C)
NetD68_2: D68.2(A) R476.2
NetD69_1: D69.1(K) Q52.2(C) Q52.4(C)
NetD69_2: D69.2(A) R485.2
NetD70_1: D70.1(K) Q53.2(C) Q53.4(C)
NetD70_2: D70.2(A) R486.2
NetD71_1: D71.1(K) Q54.2(C) Q54.4(C)
NetD71_2: D71.2(A) R495.2
NetD72_1: D72.1(K) Q55.2(C) Q55.4(C)
NetD72_2: D72.2(A) R496.2
NetQ40_1: Q40.1(B) R427.2
NetQ41_1: Q41.1(B) R428.2
NetQ42_1: Q42.1(B) R437.2
NetQ43_1: Q43.1(B) R438.2
NetQ44_1: Q44.1(B) R447.2
NetQ45_1: Q45.1(B) R448.2
NetQ46_1: Q46.1(B) R457.2
NetQ47_1: Q47.1(B) R458.2
NetQ48_1: Q48.1(B) R467.2
NetQ49_1: Q49.1(B) R468.2
NetQ50_1: Q50.1(B) R477.2
NetQ51_1: Q51.1(B) R478.2
NetQ52_1: Q52.1(B) R487.2
NetQ53_1: Q53.1(B) R488.2
NetQ54_1: Q54.1(B) R497.2
NetQ55_1: Q55.1(B) R498.2

Not connected (* = marked no-connect by the designer): J10 1* 2* 22*; J18 20*

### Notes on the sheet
- if faked A1_CELL applied ,A1_VC15-A1_VC14 only measured by BBP/BBN not A1_VC15/A1_VC14. A1_VC16-A1_VC15 measured by bypass resistor

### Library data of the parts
C103-C119 C121 C122 = CMP-0079993-1: CAP, CERM, 0.01 µF, 100 V,+/- 10%, X7R, 0603; Manufacturer: Wurth Elektronik; TaMin_C: -55°C; Polarized: N; SizeAreaWB_mm2: 4.68; U/M: EA; Value: 0.01uF; TaMax_C: 105°C; SizeZ_mm: 1; SizeX_mm: 1.6; SizeY_mm: 0.8; Value2: 100V; SizeArea_mm2: 1.28; AEC Category: Q200; ValueDisplayed: 0.01µF
C190-C206 C208-C210 C212-C221 C223 = CMP-0007138-4: as C13 on sheet BMU_A2_bq79616
C207 C211 C222 = CMP-0007138-4: CAP, CERM, 0.47 uF, 16 V, +/- 10%, X7R, AEC-Q200 Grade 1, 0603; Manufacturer: MuRata; Polarized: N; Value: 0.47uF; U/M: EA; Cap_F: 470nF; Value1: Unknown; VDC_V: 16V; TaMin_C: -55°C; TaMax_C: 125°C; AEC Category: Q200; AEC Qualified: Y; AEC Grade: 1; SizeAreaWB_mm2: 4.68; SizeX_mm: 1.6; SizeY_mm: 0.8; SizeArea_mm2: 1.28
D56 = CMP-0005734-3: Diode, TVS, Uni, 70 V, 113 Vc, SMC; AEC Qualified: N; SizeAreaWB_mm2: 78.5757; SizeX_mm: 7.94; SizeArea_mm2: 46.8857; Ipp: 13.3A; RJA_CperW: 75; SizeY_mm: 5.905; Vbr_Max: 86V; SizeZ_mm: 2.62; Vbr_Min: 77.8V; Vc: 113V; Ppk: 1.5kW; AEC Category: Q101; Value1: 1500W
D57-D72 = CMP-0002947-3: LED, Red, SMD; Manufacturer: Wurth Elektronik; Value1: 0.072W; Vf_V: 2V; Angle: 140; Tjmax_C: 85°C; Type: AlInGaP; Vr_V: 5V; Io_A: 30mA; Power_TotalModule: 72mW
J10 = CMP-0087165-1: Connector Header Through Hole, Right Angle 22 position 0.100" (2.54mm); Manufacturer: Molex; Voltage_V: 250V; Current_A: 3A; ContactFinish: Gold,Nickel; Row_Count: 1
J16 = CMP-0054794-2: as J32 on sheet Transf_BMS_Communications
J18 = CMP-0075434-1: Header, 100mil, 20x1, Gold, TH; Manufacturer: Wurth Elektronik; Pitch_mm: 2.54; Cert_VDE: N; Gender: Male; Cert_CSA: Y; Current_A: 6.3A; Voltage_V: 550V; CT: False; Row_Count: 1; CNHeader: True
Q40-Q55 = CMP-0000384-2: Transistor, NPN, 45 V, 1 A, SOT-89; Manufacturer: Diodes Inc.; TaMax_C: 150°C; Value1: 1 A; Vcesat1_V: 80mV; SizeX_mm: 4.1; SizeY_mm: 4.5; TaMin_C: -55°C; IcRated_A: 1A; CompType: BJT; SizeZ_mm: 1.5; Value: 45 V; SizeArea_mm2: 18.45; NPN: 1; Vceo_V: 45V; PNP: 0; AEC Category: Q101; SizeAreaWB_mm2: 28.05; U/M: EA
R417 R418 = CMP-0025697-4: RES, 0, 5%, 0.1 W, AEC-Q200 Grade 0, 0603; Manufacturer: Vishay-Dale; Power_W: 100mW; TempCo: 200 ppm/C; Value_Code: 0000; Value: 0; EIA_Code: E24; SizeX_mm: 1.6; SizeY_mm: 0.8; SizeZ_mm: 1; Value2: 0.1W; SizeArea_mm2: 1.28; AEC Qualified: Y; VDC_V: 75V; AEC Category: Q200
R419-R422 R429-R432 R439-R442 R449-R452 R459-R462 R469-R472 R479-R482 R489-R492 R499 R500 = CMP-0083073-1: RES, 30.0, 1%, 0.5 W, 1210; Manufacturer: Yageo; Power_W: 500mW; TempCo: 100 ppm/C; SizeAreaWB_mm2: 14.7; Value_Code: 30R0; Value: 30.0; Res_ohm: 30; SizeX_mm: 3.2; SizeY_mm: 2.5; SizeZ_mm: 1.35; Value2: 0.5W; SizeArea_mm2: 8; AEC Qualified: N; VDC_V: 200V; AEC Category: Q200
R423 R424 R433 R434 R443 R444 R453 R454 R463 R464 R473 R474 R483 R484 R493 R494 R501 = CMP-0023361-3: RES, 100, 0.1%, 0.1 W, AEC-Q200 Grade 0, 0603; Manufacturer: Panasonic; Power_W: 100mW; TempCo: 25 ppm/C; Value_Code: 100R; U/M: EA; Value: 100; EIA_Code: E192; SizeX_mm: 1.6; SizeY_mm: 0.8; SizeZ_mm: 1; Value2: 0.1W; SizeArea_mm2: 1.28; AEC Qualified: Y; VDC_V: 75V; AEC Grade: 0; AEC Category: Q200
R425 R426 R435 R436 R445 R446 R455 R456 R465 R466 R475 R476 R485 R486 R495 R496 = CMP-0025729-4: as R30 on sheet BMU_A2_bq79616
R427 R428 R437 R438 R447 R448 R457 R458 R467 R468 R477 R478 R487 R488 R497 R498 = CMP-0026902-3: RES, 300, 5%, 0.063 W, AEC-Q200 Grade 0, 0402; Manufacturer: Vishay-Dale; Power_W: 63mW; TempCo: 200 ppm/C; Value_Code: 300R; Value: 300; EIA_Code: E24; SizeX_mm: 1; SizeY_mm: 0.5; SizeZ_mm: 0.6; Value2: 0.063W; AEC Qualified: Y; VDC_V: 50V; AEC Category: Q200; AEC Grade: 0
